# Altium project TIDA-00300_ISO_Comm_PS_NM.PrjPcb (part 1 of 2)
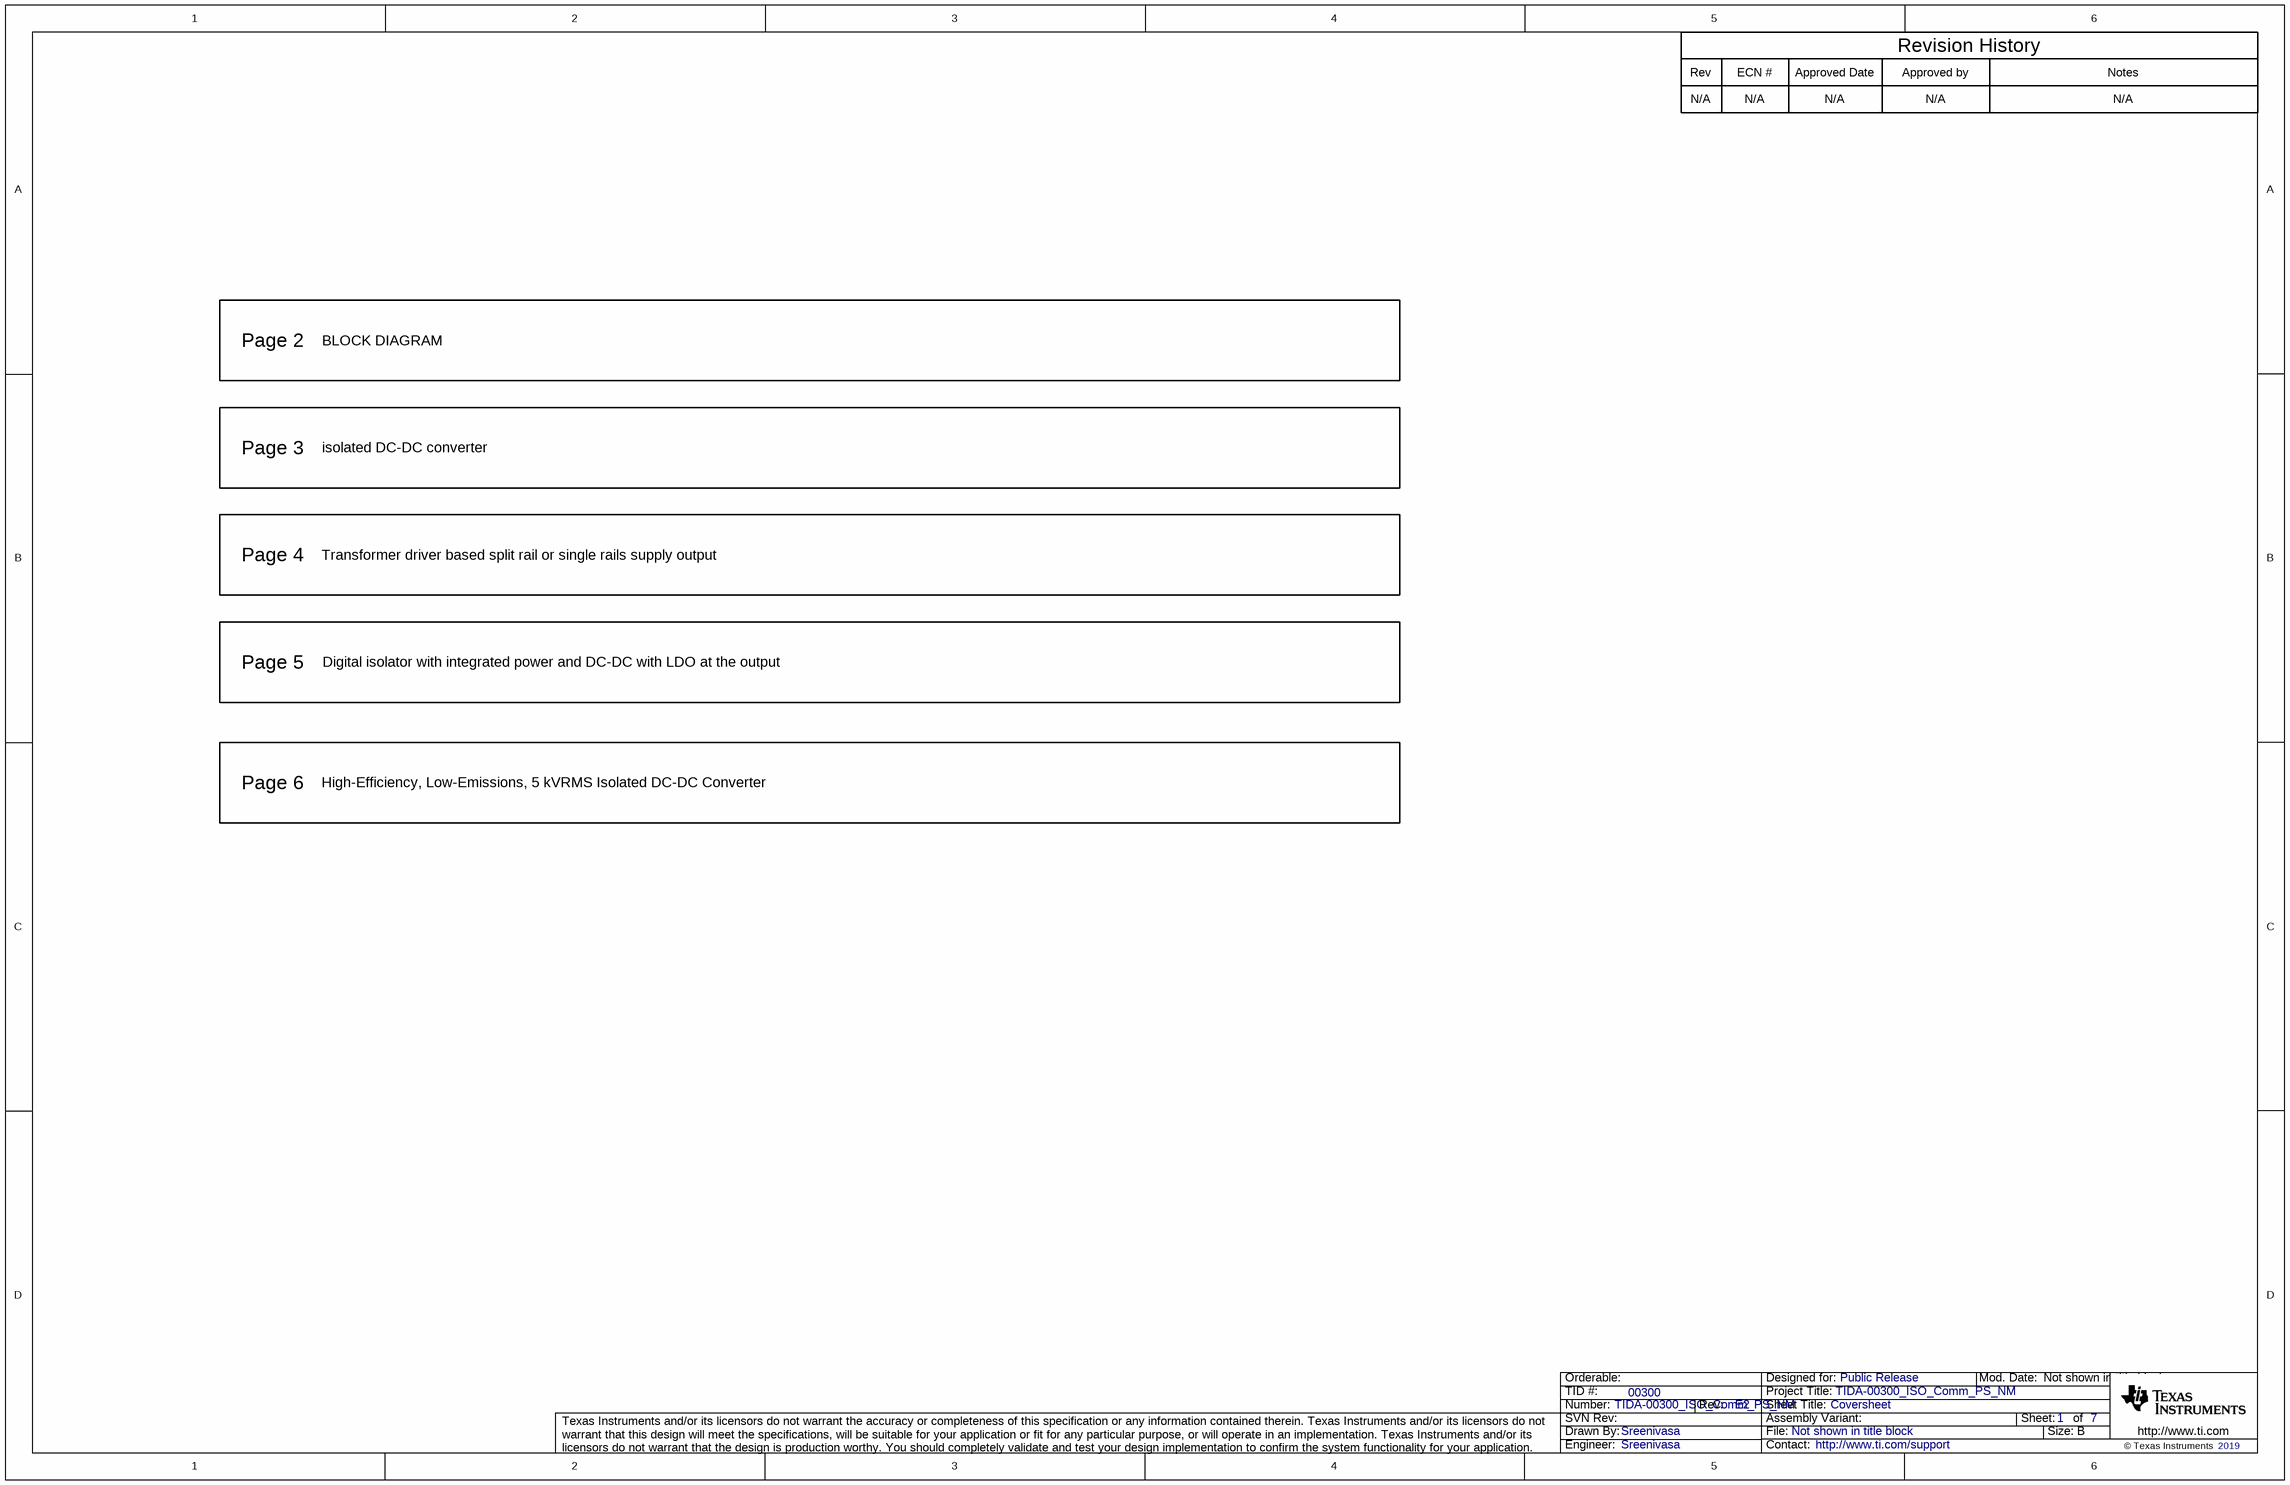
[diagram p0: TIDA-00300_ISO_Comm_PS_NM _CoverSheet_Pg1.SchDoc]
CopyrightYear: 2019; PCB_Layout: Avinash N; PCB_Rev: E2; PRJ_Customer: Public Release; PRJ_Engineer: Sreenivasa; PRJ_Number: TIDA-00300_ISO_Comm_PS_NM; PRJ_Title: TIDA-00300_ISO_Comm_PS_NM; SCH_Rev: E2; TechSupport: http://www.ti.com/support; TID: 00300
7 sheets, 304 parts. Net scope: global (net labels, ports and power ports of the same name join across sheets).
Board file: TIDA-00300_ISO_Comm_PS_NM.PcbDoc
Sheets:
  TIDA-00300_ISO_Comm_PS_NM _CoverSheet_Pg1.SchDoc
  TIDA-00300_ISO_Comm_PS_NM_ Block Diagram_Pg2.SchDoc
  TIDA-00300_ISO_Comm_PS_NM_Pg3.SchDoc
  TIDA-00300_ISO_Comm_PS_NM_Pg4.SchDoc
  TIDA-00300_ISO_Comm_PS_NM_Pg5.SchDoc
  TIDA-00300_ISO_Comm_PS_NM_Pg6.SchDoc
  TIDA-00300_ISO_Comm_PS_NM_EVM_Hardware_Pg7.SchDoc

## Sheet TIDA-00300_ISO_Comm_PS_NM _CoverSheet_Pg1.SchDoc: Coversheet
size 431 x 279 mm; Date: Not shown in title block; ApprovedBy: Not shown in title block; CheckedBy: Not shown in title block; Author: Not shown in title block; CompanyName: Not shown in title block; DrawnBy: Sreenivasa; Engineer: Not shown in title block; Organization: Not shown in title block; Address1: Not shown in title block; Address2: Not shown in title block; Address3: Not shown in title block; Address4: Not shown in title block; DocumentNumber: 1; Revision: Use project parameter SCH_Rev; SheetNumber: 1; SheetTotal: 7; PageSetup: Record=PageOptions¦CenterHorizontal=True¦CenterVertical=True¦PrintScale=1.00¦XCorrection=1.00¦YCorrection=1.00¦PrintKind=0¦BorderSize=5000000¦LeftOffset=0¦BottomOffset=0¦Orientation=2¦PaperLength=1000¦PaperWidth=1000¦Scale=100¦PaperSource=15¦PrintQuality=600¦MediaType=1¦DitherType=10¦PaperKind=Letter¦PrintScaleMode=1

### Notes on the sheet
- Rev
- N/A
- ECN #
- Approved Date
- Approved by
- Revision History
- Notes
- Page 2
- BLOCK DIAGRAM
- Page 3
- isolated DC-DC converter
- Page 4
- Transformer driver based split rail or single rails supply output
- Page 5
- Digital isolator with integrated power and DC-DC with LDO at the output
- Page 6
- High-Efficiency, Low-Emissions, 5 kVRMS Isolated DC-DC Converter

## Sheet TIDA-00300_ISO_Comm_PS_NM_ Block Diagram_Pg2.SchDoc: Block Diagram
size 431 x 279 mm; Date: Not shown in title block; ApprovedBy: Not shown in title block; CheckedBy: Not shown in title block; Author: Not shown in title block; CompanyName: Not shown in title block; DrawnBy: Sreenivasa; Engineer: Sreenivasa; Organization: Not shown in title block; Address1: Not shown in title block; Address2: Not shown in title block; Address3: Not shown in title block; Address4: Not shown in title block; DocumentNumber: 1; Revision: Use project parameter SCH_Rev; SheetNumber: 2; SheetTotal: 7; PageSetup: Record=PageOptions¦CenterHorizontal=True¦CenterVertical=True¦PrintScale=1.00¦XCorrection=1.00¦YCorrection=1.00¦PrintKind=0¦BorderSize=5000000¦LeftOffset=0¦BottomOffset=0¦Orientation=2¦PaperLength=1000¦PaperWidth=1000¦Scale=100¦PaperSource=15¦PrintQuality=600¦MediaType=1¦DitherType=10¦PaperKind=Letter¦PrintScaleMode=1
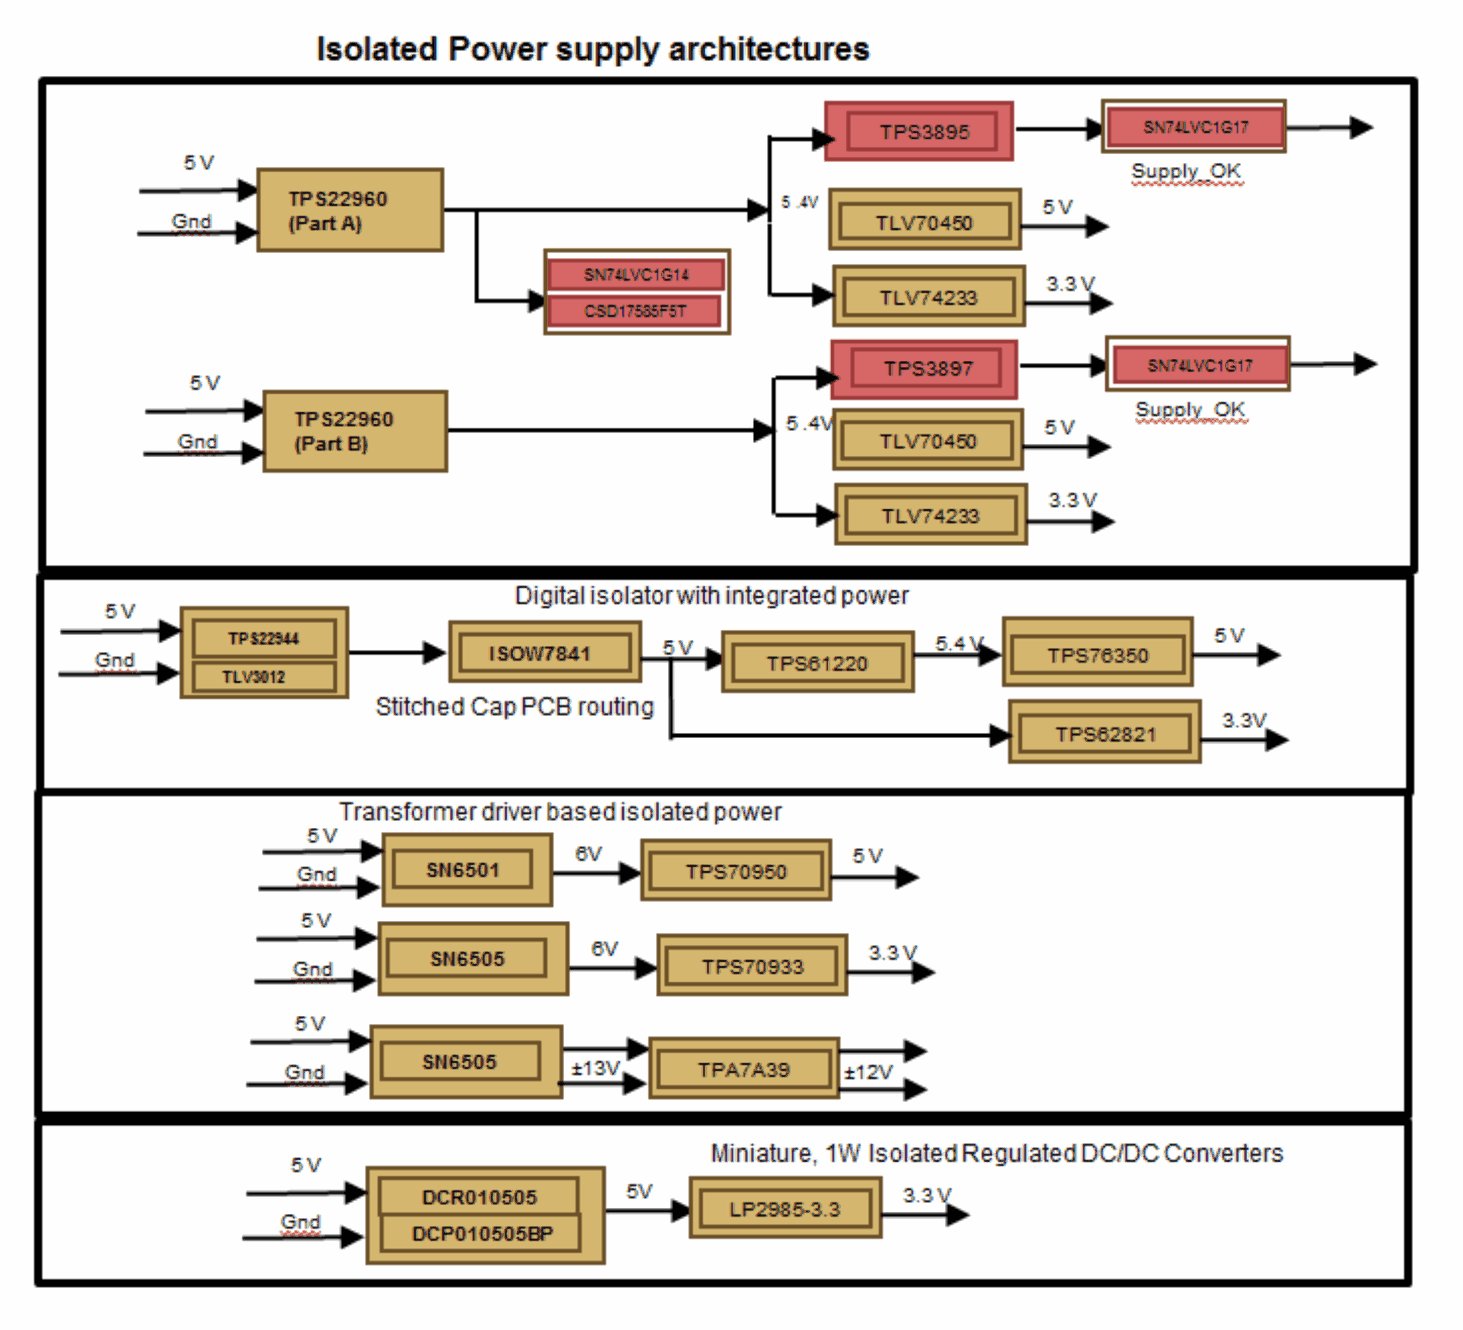
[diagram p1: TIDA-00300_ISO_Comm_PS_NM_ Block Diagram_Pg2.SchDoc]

## Sheet TIDA-00300_ISO_Comm_PS_NM_Pg3.SchDoc
size 431 x 279 mm; Date: Not shown in title block; ApprovedBy: Not shown in title block; CheckedBy: Not shown in title block; Author: Not shown in title block; CompanyName: Not shown in title block; DrawnBy: Sreenivasa; Engineer: Not shown in title block; Organization: Not shown in title block; Address1: Not shown in title block; Address2: Not shown in title block; Address3: Not shown in title block; Address4: Not shown in title block; DocumentNumber: 1; Revision: Use project parameter SCH_Rev; SheetNumber: 3; SheetTotal: 7; PageSetup: Record=PageOptions¦CenterHorizontal=True¦CenterVertical=True¦PrintScale=0.62¦XCorrection=1.00¦YCorrection=1.00¦PrintKind=0¦BorderSize=5000000¦LeftOffset=0¦BottomOffset=0¦Orientation=2¦PaperLength=1000¦PaperWidth=1000¦Scale=100¦PaperSource=15¦PrintQuality=600¦MediaType=1¦DitherType=10¦PrintScaleMode=1¦PaperKind=Letter
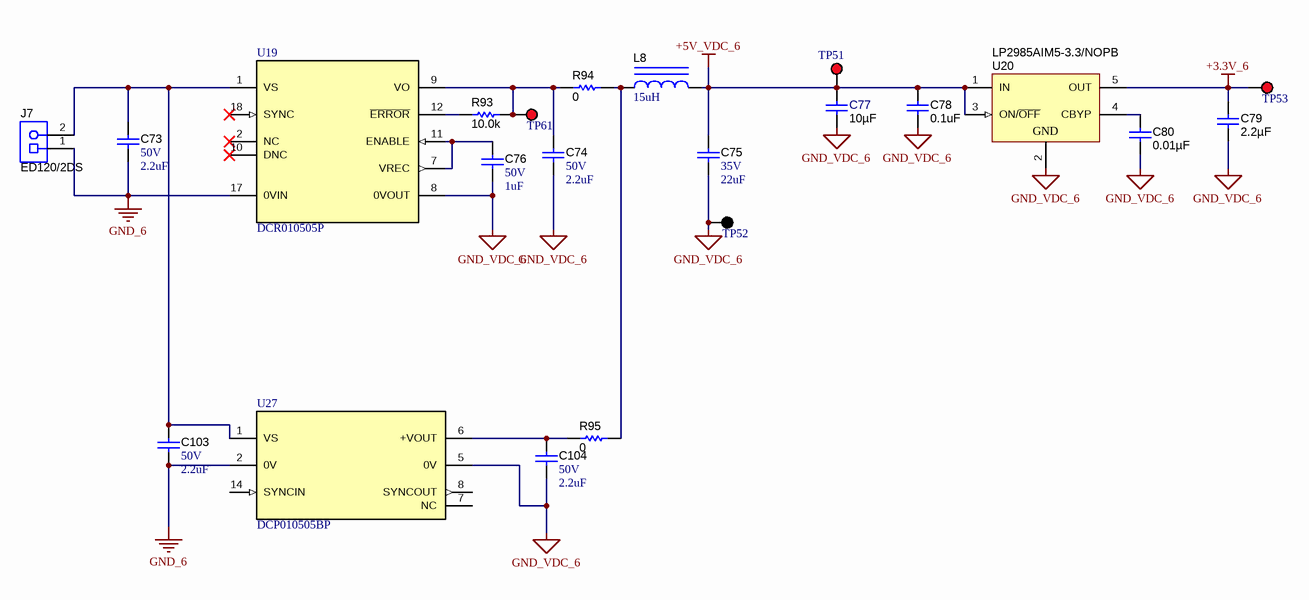
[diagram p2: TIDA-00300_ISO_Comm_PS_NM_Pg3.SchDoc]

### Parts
C73  VDC_V: 50V  ValueDisplayed: 2.2uF  [0805_HV]  (hidden comment: C2012X5R1H225K125AB)
C74  VDC_V: 50V  ValueDisplayed: 2.2uF  [0805_HV]  (hidden comment: C2012X5R1H225K125AB)
C75  VDC_V: 35V  ValueDisplayed: 22uF  [0805_HV]  (hidden comment: C2012X5R1V226M125AC)
C76  VDC_V: 50V  ValueDisplayed: 1uF  [0603]  (hidden comment: UMK107AB7105KA-T)
C77  ValueDisplayed: 10µF  [0603]  (hidden comment: C1608X5R1A106M)
C78  value 0.1uF  [0402]  (hidden comment: GRM155R71C104JA88D)
C79  ValueDisplayed: 2.2µF  [0603]  (hidden comment: C0603C225K8PACTU)
C80  ValueDisplayed: 0.01µF  [0603]  (hidden comment: C1608C0G1E103J)
C103  VDC_V: 50V  ValueDisplayed: 2.2uF  [0805_HV]  (hidden comment: C2012X5R1H225K125AB)
C104  VDC_V: 50V  ValueDisplayed: 2.2uF  [0805_HV]  (hidden comment: C2012X5R1H225K125AB)
J7  ED120/2DS  [CONN_ED120-2DS]
L8  ValueDisplayed: 15uH  [LQH3NP_G0]  (hidden comment: LQH3NPN150NG0)
R93  ValueDisplayed: 10.0k  [0402]  (hidden comment: CRCW040210K0FKED)
R94  value 0  [0603]  (hidden comment: CRCW06030000Z0EA)
R95  value 0  [0603]  (hidden comment: CRCW06030000Z0EA)
TP51  5000  [Keystone5000]  (value not drawn)
TP52  5001  [Keystone5001]  (value not drawn)
TP53  5000  [Keystone5000]  (value not drawn)
TP61  5000  [Keystone5000]  (value not drawn)
U19  DCR010505P  [NVE0010A]
U20  LP2985AIM5-3.3/NOPB  [MF05A_N]
U27  DCP010505BP  [NVA0007A]

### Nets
+3.3V_6: C79.1 TP53.1 U20.5(OUT)
+5V_VDC_6: C75.1 C77.1 C78.1 L8.2 TP51.1 U20.1(IN) U20.3(ON/~{OFF})
GND_6: C73.2 C103.2 J7.1 U19.17(0VIN) U27.2(0V)
GND_VDC_6: C74.2 C75.2 C76.2 C77.2 C78.2 C79.2 C80.2 C104.2 TP52.1 U19.8(0VOUT) U20.2(GND) U27.5(0V)
NetC73_1: C73.1 C103.1 J7.2 U19.1(VS) U27.1(VS)
NetC74_1: C74.1 R93.2 R94.2 TP61.1 U19.9(VO)
NetC76_1: C76.1 U19.7(VREC) U19.11(ENABLE)
NetC80_1: C80.1 U20.4(CBYP)
NetC104_1: C104.1 R95.2 U27.6(+VOUT)
NetL8_1: L8.1 R94.1 R95.1
NetR93_1: R93.1 U19.12(~{ERROR})

Not connected (* = marked no-connect by the designer): U19 2(NC)* 10(DNC)* 18(SYNC)*; U27 7(NC) 8(SYNCOUT) 14(SYNCIN)

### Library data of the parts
C73 C74 C103 C104 = CMP-0007836-1: CAP, CERM, 2.2 uF, 50 V, +/- 10%, X5R, 0805; Manufacturer: TDK; TaMin_C: -55°C; ESR_ohm: 3.66m; Polarized: N; SizeAreaWB_mm2: 6.75; Value1: 0.00366 ohm; U/M: EA; Value: 2.2uF; TaMax_C: 85°C; SizeZ_mm: 1.45; SizeX_mm: 2; SizeY_mm: 1.25; Cap_Case: 0805; SizeArea_mm2: 2.5; Cap_F: 2.2µF; IRMS_A: 3.41207A; AEC Category: Q200
C75 = CMP-0007844-1: CAP, CERM, 22 uF, 35 V, +/- 20%, X5R, 0805; Manufacturer: TDK; TaMin_C: -55°C; ESR_ohm: 2.05m; Polarized: N; SizeAreaWB_mm2: 6.75; Value1: 0.00205 ohm; U/M: EA; Value: 22uF; TaMax_C: 85°C; SizeZ_mm: 1.45; SizeX_mm: 2; SizeY_mm: 1.25; Cap_Case: 0805; SizeArea_mm2: 2.5; Cap_F: 22µF; IRMS_A: 4.55587A; AEC Category: Q200
C76 = CMP-0007508-1: CAP, CERM, 1 uF, 50 V, +/- 10%, X7R, 0603; Manufacturer: Taiyo Yuden; TaMin_C: -55°C; Polarized: N; SizeAreaWB_mm2: 4.68; Value1: Unknown; U/M: EA; Value: 1uF; TaMax_C: 125°C; SizeZ_mm: 1; SizeX_mm: 1.6; SizeY_mm: 0.8; SizeArea_mm2: 1.28; Cap_F: 1µF; AEC Category: Q200
C77 = C1608X5R1A106M: CAP, CERM, 10uF, 10V, +/-20%, X5R, 0603; Manufacturer: TDK; Polarized: N; CompType: Capacitor; U/M: EA; Cap_F: 0.00001; Tolerance_%: 20; ESR_Ohm: 0.0078; Value1: 0.0078 ohm; VDC_V: 10; IRMS_A: 1.85; TaMin_C: -55; TaMax_C: 85
C78 = 0402YC132KAT2A: CAP CER 0.1UF 16V 5% X7R 0402; Manufacturer: Murata Electronics North America; Polarized: N; CompType: Capacitor; U/M: EA; Cap_F: 0.0000000013; Tolerance_%: 10; VDC_V: 16; TaMin_C: -55; TaMax_C: 125
C79 = C0603C225K8PACTU: CAP, CERM, 2.2uF, 10V, +/-10%, X5R, 0603; Manufacturer: Kemet; Polarized: N; CompType: Capacitor; U/M: EA; Cap_F: 0.0000022; Tolerance_%: 10; Value1: Unknown; TaMin_C: -55; TaMax_C: 85
C80 = C1608C0G1E103J: CAP, CERM, 0.01uF, 25V, +/-5%, C0G/NP0, 0603; Manufacturer: TDK; Polarized: N; CompType: Capacitor; U/M: EA; Cap_F: 0.00000001; Tolerance_%: 5; VDC_V: 25; TaMin_C: -55; TaMax_C: 125
J7 = ED120/2DS: TERMINAL BLOCK 5.08MM VERT 2POS, TH; Manufacturer: On-Shore Technology; SymbolCreator: a0412235; U/M: EA
L8 = CMP-0058850-1: Inductor, Wirewound, Ferrite, 15 uH, 0.37 A, 0.91 ohm, SMD; Manufacturer: MuRata; Isat: 0.37A @ 30% inductance drop; Irms: 0.475A @ 40C rise; Green_Lifecycle: Not Set; SizeAreaWB_mm2: 16; DCR_ohm: 0.91; Green_REACh: Incomplete; Value: 15uH; Imax_A: 370mA; SizeZ_mm: 1; SizeX_mm: 3; Value2: 0.37A; SizeArea_mm2: 9; Ind_H: 15µH; AEC Category: Q200
R93 = CRCW040210K0FKED: RES, 10.0 k, 1%, 0.063 W, 0402; Manufacturer: Vishay-Dale; CompType: Resistor; Value: 10.0k; Res_ohm: 10000; Value_Code: 10k0; Tolerance_%: 1; Power_W: 0.063; Value2: 0.063W; VDC_V: 50; TempCo: 100 ppm/C; SizeArea_mm2: 0.5; SizeZ_mm: 0.6; EIA_Code: E96; U/M: EA; AEC Category: Q200; Green_Lifecycle: Active; Green_REACh: Passed
R94 R95 = CRCW06030000Z0EA: RES, 0 ohm, 5%, 0.1W, 0603; Manufacturer: Vishay-Dale; CompType: Resistor; Value_Code: 0000; Tolerance_%: 5; Power_W: 0.1; VDC_V: 75; TempCo: 200 ppm/C; EIA_Code: E24; U/M: EA
TP51 TP53 TP61 = 5000: Test Point, Miniature, Red, TH; Manufacturer: Keystone; CompType: Test Point Loop; ContactFinish: Silver; Green_Lifecycle: Active; Green_REACh: Passed
TP52 = 5001: Test Point, Miniature, Black, TH; Manufacturer: Keystone; CompType: Test Point Loop; ContactFinish: Silver; Green_Lifecycle: Active; Green_REACh: Passed
U19 = CMP-0030829-1: Miniature, 1 W Isolated Regulated DC-DC Converter, -40 to 85 degC, 10-pin DIP (NVE10), Pb-Free (RoHS); Manufacturer: Texas Instruments; Vout(Max)(V): 5.1; Vin(Min)(V): 4.5; Regulated Outputs(#): 1; Vout(Min)(V): 4.9; SubFamily: 1 W & 2 W Miniature; Iout(Max)(A): 0.2; Vin(Max)(V): 5.5
U20 = LP2985AIM5-3.3/NOPB: Micropower 150 mA Low-Noise Ultra Low-Dropout Regulator, 5-pin SOT-23, Pb-Free; Manufacturer: Texas Instruments; PackageTopMarking: L0RA*XTT; PowerWise: N; CompType: LDO IC
U27 = CMP-0030762-1: Miniature, 1 W Isolated Unregulated DC-DC Converter, -40 to 100 degC, 7-pin DIP (NVA7), Pb-Free (RoHS); Manufacturer: Texas Instruments; SubFamily: 1 W & 2 W Miniature; Vin(Max)(V): 5.5; Vout(Max)(V): 5.25; Vin(Min)(V): 4.5; Regulated Outputs(#): 1; Vout(Min)(V): 4.75; Iout(Max)(A): 0.2

## Sheet TIDA-00300_ISO_Comm_PS_NM_Pg4.SchDoc
size 431 x 279 mm; Date: Not shown in title block; ApprovedBy: Not shown in title block; CheckedBy: Not shown in title block; Author: Not shown in title block; CompanyName: Not shown in title block; DrawnBy: Sreenivasa; Engineer: Not shown in title block; Organization: Not shown in title block; Address1: Not shown in title block; Address2: Not shown in title block; Address3: Not shown in title block; Address4: Not shown in title block; DocumentNumber: 1; Revision: Use project parameter SCH_Rev; SheetNumber: 4; SheetTotal: 7; PageSetup: Record=PageOptions¦CenterHorizontal=True¦CenterVertical=True¦PrintScale=0.62¦XCorrection=1.00¦YCorrection=1.00¦PrintKind=0¦BorderSize=5000000¦LeftOffset=0¦BottomOffset=0¦Orientation=2¦PaperLength=1000¦PaperWidth=1000¦Scale=100¦PaperSource=15¦PrintQuality=600¦MediaType=1¦DitherType=10¦PrintScaleMode=1¦PaperKind=Letter
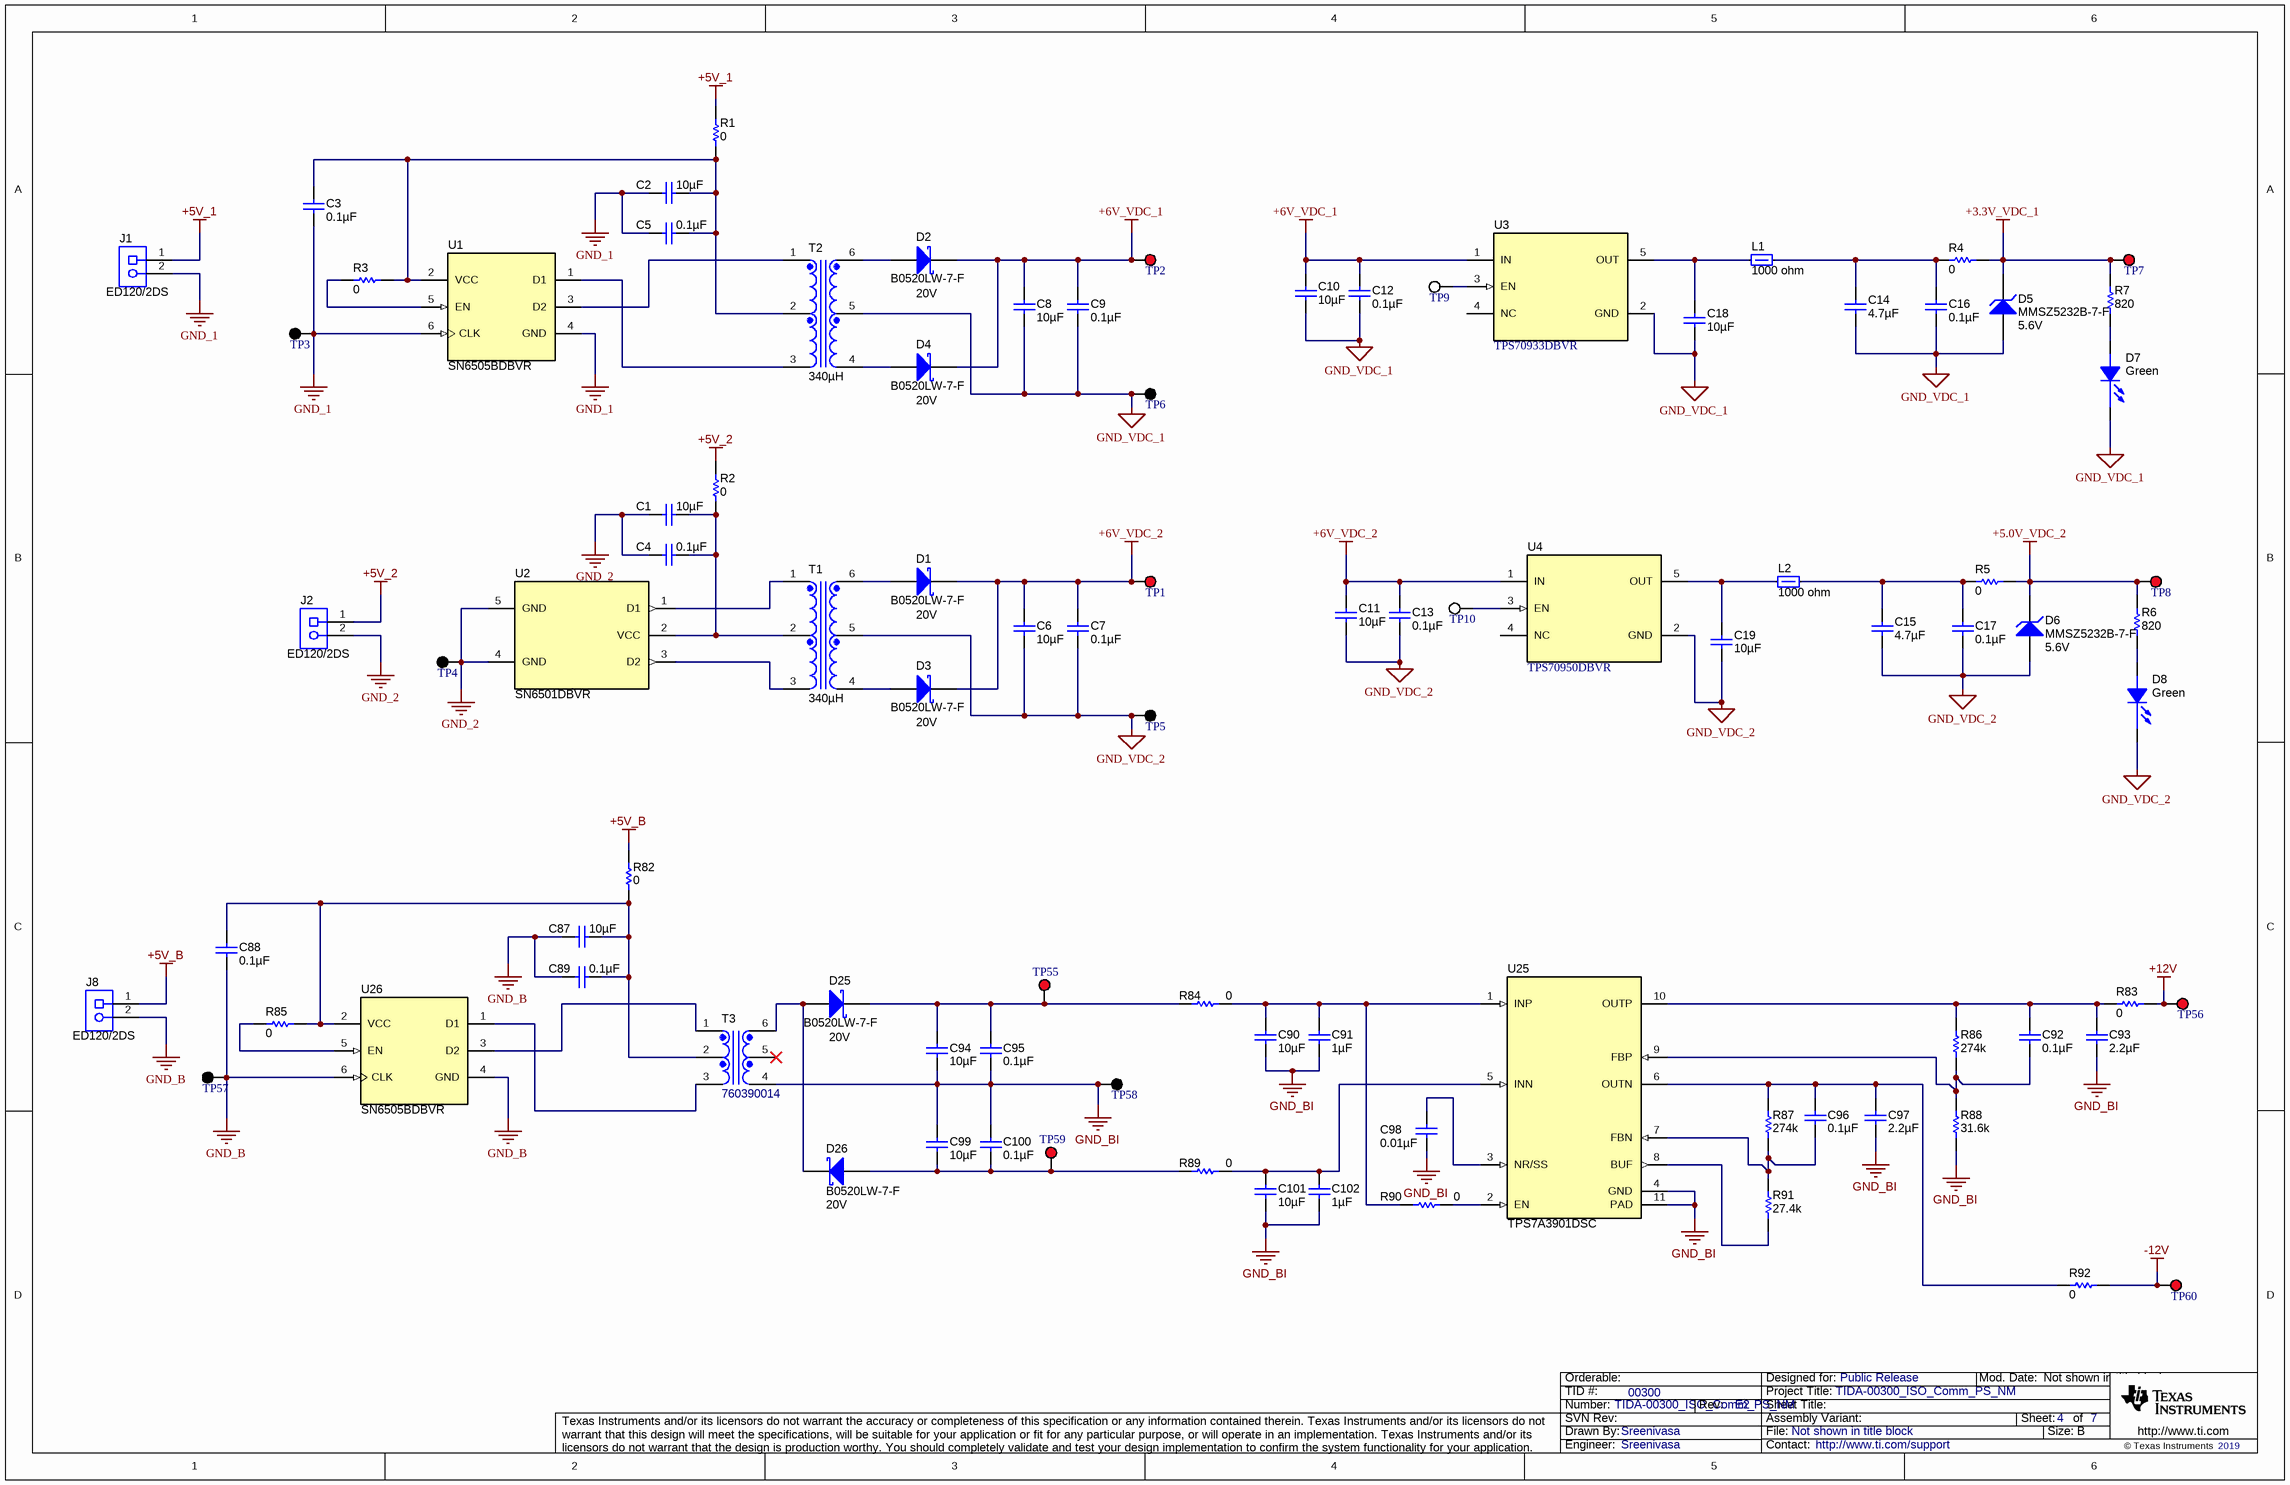
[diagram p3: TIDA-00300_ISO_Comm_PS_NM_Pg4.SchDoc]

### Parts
C1  ValueDisplayed: 10µF  [1210]
C2  ValueDisplayed: 10µF  [1210]
C3  ValueDisplayed: 0.1µF  [0603]
C4  ValueDisplayed: 0.1µF  [0603]
C5  ValueDisplayed: 0.1µF  [0603]
C6  ValueDisplayed: 10µF  [1210]
C7  ValueDisplayed: 0.1µF  [0603]
C8  ValueDisplayed: 10µF  [1210]
C9  ValueDisplayed: 0.1µF  [0603]
C10  ValueDisplayed: 10µF  [1210]
C11  ValueDisplayed: 10µF  [1210]
C12  ValueDisplayed: 0.1µF  [0603]
C13  ValueDisplayed: 0.1µF  [0603]
C14  ValueDisplayed: 4.7µF  [0805_HV]
C15  ValueDisplayed: 4.7µF  [0805_HV]
C16  ValueDisplayed: 0.1µF  [0603]
C17  ValueDisplayed: 0.1µF  [0603]
C18  ValueDisplayed: 10µF  [1210]
C19  ValueDisplayed: 10µF  [1210]
C87  ValueDisplayed: 10µF  [1210]
C88  ValueDisplayed: 0.1µF  [0603]
C89  ValueDisplayed: 0.1µF  [0603]
C90  ValueDisplayed: 10µF  [1206_180]  (hidden comment: C1210C106M5RACTU)
C91  ValueDisplayed: 1µF  [0603]  (hidden comment: C1608X7R1E105K080AB)
C92  ValueDisplayed: 0.1µF  [0603]  (hidden comment: GMK107BJ104KAHT)
C93  ValueDisplayed: 2.2µF  [0805_HV]  (hidden comment: C0805C225K8RACTU)
C94  ValueDisplayed: 10µF  [1210]
C95  ValueDisplayed: 0.1µF  [0603]
C96  ValueDisplayed: 0.1µF  [0603]  (hidden comment: GMK107BJ104KAHT)
C97  ValueDisplayed: 2.2µF  [0805_HV]  (hidden comment: C0805C225K8RACTU)
C98  ValueDisplayed: 0.01µF  [0603]  (hidden comment: GRM188R70J103KA01D)
C99  ValueDisplayed: 10µF  [1210]
C100  ValueDisplayed: 0.1µF  [0603]
C101  ValueDisplayed: 10µF  [1206_180]  (hidden comment: C1210C106M5RACTU)
C102  ValueDisplayed: 1µF  [0603]  (hidden comment: C1608X7R1E105K080AB)
D1  B0520LW-7-F  value 20V  [SOD-123]
D2  B0520LW-7-F  value 20V  [SOD-123]
D3  B0520LW-7-F  value 20V  [SOD-123]
D4  B0520LW-7-F  value 20V  [SOD-123]
D5  MMSZ5232B-7-F  value 5.6V  [SOD-123]
D6  MMSZ5232B-7-F  value 5.6V  [SOD-123]
D7  value Green  [LED0603AA]
D8  value Green  [LED0603AA]
D25  B0520LW-7-F  value 20V  [SOD-123]
D26  B0520LW-7-F  value 20V  [SOD-123]
J1  ED120/2DS  [CONN_ED120-2DS]
J2  ED120/2DS  [CONN_ED120-2DS]
J8  ED120/2DS  [CONN_ED120-2DS]
L1  value 1000 ohm  [MMZ1608_095]  (hidden comment: MMZ1608B102CTA00)
L2  value 1000 ohm  [MMZ1608_095]  (hidden comment: MMZ1608B102CTA00)
R1  value 0  [0603]  (hidden comment: CRCW06030000Z0EA)
R2  value 0  [0603]  (hidden comment: CRCW06030000Z0EA)
R3  value 0  [0603]  (hidden comment: CRCW06030000Z0EA)
R4  value 0  [0603]  (hidden comment: CRCW06030000Z0EA)
R5  value 0  [0603]  (hidden comment: CRCW06030000Z0EA)
R6  ValueDisplayed: 820  [0603]  (hidden comment: RC0603FR-07820RL)
R7  ValueDisplayed: 820  [0603]  (hidden comment: RC0603FR-07820RL)
R82  value 0  [0603]  (hidden comment: CRCW06030000Z0EA)
R83  ValueDisplayed: 0  [0603]  (hidden comment: CRCW06030000Z0EA)
R84  ValueDisplayed: 0  [0603]  (hidden comment: CRCW06030000Z0EA)
R85  value 0  [0603]  (hidden comment: CRCW06030000Z0EA)
R86  ValueDisplayed: 274k  [0603]  (hidden comment: CRCW0603274KFKEA)
R87  ValueDisplayed: 274k  [0603]  (hidden comment: CRCW0603274KFKEA)
R88  ValueDisplayed: 31.6k  [0603]  (hidden comment: CRCW060331K6FKEA)
R89  ValueDisplayed: 0  [0603]  (hidden comment: CRCW06030000Z0EA)
R90  ValueDisplayed: 0  [0603]  (hidden comment: CRCW06030000Z0EA)
R91  ValueDisplayed: 27.4k  [0603]  (hidden comment: CRCW060327K4FKEA)
R92  ValueDisplayed: 0  [0603]  (hidden comment: CRCW06030000Z0EA)
T1  ValueDisplayed: 340µH  [Wurth_750313638]  (hidden comment: 750313638)
T2  ValueDisplayed: 340µH  [Wurth_750313638]  (hidden comment: 750313638)
T3  760390014  [Wurth_760390013]
TP1  5000  [Keystone5000]  (value not drawn)
TP2  5000  [Keystone5000]  (value not drawn)
TP3  5001  [Keystone5001]  (value not drawn)
TP4  5001  [Keystone5001]  (value not drawn)
TP5  5001  [Keystone5001]  (value not drawn)
TP6  5001  [Keystone5001]  (value not drawn)
TP7  5000  [Keystone5000]  (value not drawn)
TP8  5000  [Keystone5000]  (value not drawn)
TP9  5002  [Keystone5002]  (value not drawn)
TP10  5002  [Keystone5002]  (value not drawn)
TP55  5000  [Keystone5000]  (value not drawn)
TP56  5000  [Keystone5000]  (value not drawn)
TP57  5001  [Keystone5001]  (value not drawn)
TP58  5001  [Keystone5001]  (value not drawn)
TP59  5000  [Keystone5000]  (value not drawn)
TP60  5000  [Keystone5000]  (value not drawn)
U1  SN6505BDBVR  [DBV0006A_N]
U2  SN6501DBVR  [DBV0005A_N]
U3  TPS70933DBVR  [DBV0005A_N]
U4  TPS70950DBVR  [DBV0005A_N]
U25  TPS7A3901DSC  [DSC0010J]
U26  SN6505BDBVR  [DBV0006A_N]

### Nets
+3.3V_VDC_1: D5.1(K) R4.2 R7.2 TP7.1
+5.0V_VDC_2: D6.1(K) R5.2 R6.2 TP8.1
+5V_1: J1.1 R1.2
+5V_2: J2.1 R2.2
+5V_B: J8.1 R82.2
+6V_VDC_1: C8.1 C9.1 C10.2 C12.1 D2.1(K) D4.1(K) TP2.1 U3.1(IN)
+6V_VDC_2: C6.1 C7.1 C11.2 C13.1 D1.1(K) D3.1(K) TP1.1 U4.1(IN)
+12V: R83.2 TP56.1
-12V: R92.2 TP60.1
GND_1: C2.1 C3.1 C5.1 J1.2 TP3.1 U1.4(GND) U1.6(CLK)
GND_2: C1.1 C4.1 J2.2 TP4.1 U2.4(GND) U2.5(GND)
GND_B: C87.1 C88.1 C89.1 J8.2 TP57.1 U26.4(GND) U26.6(CLK)
GND_BI: C90.1 C91.2 C93.2 C94.2 C95.2 C97.2 C98.2 C99.1 C100.1 C101.1 C102.2 R88.1 T3.4 TP58.1 U25.4(GND) U25.11(PAD)
GND_VDC_1: C8.2 C9.2 C10.1 C12.2 C14.1 C16.2 C18.1 D5.2(A) D7.1(C) T2.5 TP6.1 U3.2(GND)
GND_VDC_2: C6.2 C7.2 C11.1 C13.2 C15.1 C17.2 C19.1 D6.2(A) D8.1(C) T1.5 TP5.1 U4.2(GND)
NetC1_2: C1.2 C4.2 R2.1 T1.2 U2.2(VCC)
NetC2_2: C2.2 C3.2 C5.2 R1.1 R3.1 T2.2 U1.2(VCC)
NetC14_2: C14.2 C16.1 L1.2 R4.1
NetC15_2: C15.2 C17.1 L2.2 R5.1
NetC18_2: C18.2 L1.1 U3.5(OUT)
NetC19_2: C19.2 L2.1 U4.5(OUT)
NetC87_2: C87.2 C88.2 C89.2 R82.1 R85.1 T3.2 U26.2(VCC)
NetC90_2: C90.2 C91.1 R84.2 R90.1 U25.1(INP)
NetC92_1: C92.1 C93.1 R83.1 R86.2 U25.10(OUTP)
NetC92_2: C92.2 R86.1 R88.2 U25.9(FBP)
NetC94_1: C94.1 C95.1 D25.1(K) R84.1 TP55.1
NetC96_1: C96.1 C97.1 R87.2 R92.1 U25.6(OUTN)
NetC96_2: C96.2 R87.1 R91.2 U25.7(FBN)
NetC98_1: C98.1 U25.3(NR/SS)
NetC99_2: C99.2 C100.2 D26.2(A) R89.1 TP59.1
NetC101_2: C101.2 C102.1 R89.2 U25.5(INN)
NetD1_2: D1.2(A) T1.6
NetD2_2: D2.2(A) T2.6
NetD3_2: D3.2(A) T1.4
NetD4_2: D4.2(A) T2.4
NetD7_2: D7.2(A) R7.1
NetD8_2: D8.2(A) R6.1
NetD25_2: D25.2(A) D26.1(K) T3.6
NetR3_2: R3.2 U1.5(EN)
NetR85_2: R85.2 U26.5(EN)
NetR90_2: R90.2 U25.2(EN)
NetR91_1: R91.1 U25.8(BUF)
NetT1_1: T1.1 U2.1(D1)
NetT1_3: T1.3 U2.3(D2)
NetT2_1: T2.1 U1.3(D2)
NetT2_3: T2.3 U1.1(D1)
NetT3_1: T3.1 U26.3(D2)
NetT3_3: T3.3 U26.1(D1)
NetTP9_1: TP9.1 U3.3(EN)
NetTP10_1: TP10.1 U4.3(EN)

Not connected (* = marked no-connect by the designer): T3 5*; U3 4(NC); U4 4(NC)

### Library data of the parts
C1 C2 C6 C8 C10 C11 C18 C19 C87 C94 C99 = GMK325AB7106MM-T: CAP, CERM, 10uF, 35V, +/-20%, X7R, 1210; Manufacturer: Taiyo Yuden; Polarized: N; CompType: Capacitor; U/M: EA; Cap_F: 0.00001; Tolerance_%: 20; Value1: Unknown; VDC_V: 35; TaMin_C: -55; TaMax_C: 125
C3-C5 C7 C9 C12 C13 C16 C17 C88 C89 C95 C100 = C0603C104K5RACTU: CAP, CERM, 0.1uF, 50V, +/-10%, X7R, 0603; Manufacturer: Kemet; Polarized: N; CompType: Capacitor; U/M: EA; Cap_F: 0.0000001; Tolerance_%: 10; Value1: Unknown; VDC_V: 50; TaMin_C: -55; TaMax_C: 125
C14 C15 = C2012X5R1H475K125AB: 4.7µF ±10% 50V X5R Ceramic Capacitor -55°C ~ 85°C; PartNumber: GRM21BR61H475KE51L; Manufacturer: TDK; Polarized: N; Value: 4.7uF; U/M: EA; Cap_F: 0.0000047; Tolerance_%: 10; Value1: Unknown; VDC_V: 50; TaMin_C: -55; TaMax_C: 85; Cap_Case: 0805
C90 C101 = CL31B106KBHNNNE: CAP, CERM, 10µF ±20% 50V Ceramic Capacitor X7R 1210; Manufacturer: Kemet; Polarized: N; Value: 10uF; U/M: EA; Cap_F: 0.00001; Tolerance_%: 10; Value1: Unknown; VDC_V: 50; TaMin_C: -55; TaMax_C: 125; Cap_Case: 1206; SizeArea_mm2: 5.12; SizeAreaWB_mm2: 10.92; SizeX_mm: 3.2; SizeY_mm: 1.6; SizeZ_mm: 1.8; AEC Category: Q200
C91 C102 = 885012206052: CAP, CERM,  1µF ±10% 25V Ceramic Capacitor X7R 0603; Manufacturer: TDK; Polarized: N; Value: 1uF; U/M: EA; Cap_F: 0.000001; Tolerance_%: 10; Value1: Unknown; VDC_V: 16; Value2: 16V; TaMin_C: -55; TaMax_C: 125; SizeArea_mm2: 1.28; SizeAreaWB_mm2: 4.68; SizeX_mm: 1.6; SizeY_mm: 0.8; SizeZ_mm: 1; AEC Category: Q200; Green_Lifecycle: Active; Green_REACh: Passed
C92 C96 = 06033C104JAT2A: 0.1µF ±10% 35V Ceramic Capacitor X5R 0603; Manufacturer: Taiyo Yuden; Polarized: N; Value: 0.1uF; U/M: EA; Cap_F: 0.0000001; Tolerance_%: 5; ESR_ohm: 0.05; Value1: 0.05 ohm; VDC_V: 25; Value2: 25V; TempCo: X7R; TaMin_C: -55; TaMax_C: 125; SizeArea_mm2: 1.28; SizeAreaWB_mm2: 4.68; SizeX_mm: 1.6; SizeY_mm: 0.8; SizeZ_mm: 1; AEC Category: Q200
C93 C97 = C0805C225K8RACTU: CAP, CERM, 2.2uF, 10V, +/-10%, X7R, 0805; Manufacturer: Kemet; Polarized: N; CompType: Capacitor; U/M: EA; Cap_F: 0.0000022; Tolerance_%: 10; ESR_Ohm: 0.008; Value1: 0.008 ohm; IRMS_A: 15.55; TaMin_C: -55; TaMax_C: 125; Cap_Case: 0805
C98 = GRM188R70J103KA01D: CAP, CERM, 0.01 µF, 6.3 V, +/- 10%, X7R, 0603; Manufacturer: MuRata; Polarized: N; CompType: Capacitor; Value: 0.01uF; U/M: EA; Cap_F: 0.00000001; Tolerance_%: 10; Value1: Unknown; VDC_V: 6.3; Value2: 6.3V; TaMin_C: -55; TaMax_C: 125
D1-D4 D25 D26 = MBR0520LT1G: Diode, Schottky, 20V, 0.5A, SOD-123; Manufacturer: Diodes Inc; U/M: EA; Vf_V: 0.385; Value2: 0.385V; Io_A: 0.5; Vr_V: 20; TJmax_C: 125; RJC_CperW: 150
D5 D6 = MMSZ5232B-7-F: Diode, Zener, 5.6 V, 500 mW, SOD-123; Manufacturer: Diodes Inc.; SymbolCreator: a0412235; U/M: EA; Power_W: 0.5; Vz_V: 5.6; Value1: 0.5W; RJA_CperW: 350; AEC Category: Q101
D7 D8 = LED_LG L29K-G2J1-24-Z: LED SmartLED Green 570NM; Manufacturer: OSRAM; SymbolCreator: x0120606
J1 J2 J8 = ED120/2DS: as J7 on sheet TIDA-00300_ISO_Comm_PS_NM_Pg3
L1 L2 = MMZ1608B102CTA00: Ferrite Bead, 1000 ohm @ 100 MHz, 0.3 A, 0603; Manufacturer: TDK; Imax_A: 0.3; DCR_ohm: 0.6; Value1: 0.6 ohm; Value2: 0.3A; ZTyp@100MHz_Ohm: 1000
R1-R5 R82 R85 = CRCW06030000Z0EA: as R94 on sheet TIDA-00300_ISO_Comm_PS_NM_Pg3
R6 R7 = RC0603FR-07820RL: RES, 820, 1%, 0.1 W, 0603; Manufacturer: Yageo America; CompType: Resistor; Value: 820; Value_Code: 820R; Tolerance_%: 1; Power_W: 0.1; Value2: 0.1W; VDC_V: 150; TempCo: 200 ppm/C; SizeArea_mm2: 1.28; SizeX_mm: 1.6; SizeY_mm: 0.8; U/M: EA; AEC Category: Q200
R83 R84 R89 R90 R92 = CRCW06030000Z0EA: RES, 0, 5%, 0.1 W, 0603; Manufacturer: Vishay-Dale; CompType: Resistor; Value: 0; Value_Code: 0000; Tolerance_%: 5; Power_W: 0.1; Value2: 0.1W; VDC_V: 75; TempCo: 200 ppm/C; EIA_Code: E24; U/M: EA
R86 R87 = CRCW0603274KFKEA: RES, 274 k, 1%, 0.1 W, 0603; Manufacturer: Vishay-Dale; CompType: Resistor; Value: 274k; Res_ohm: 274000; Tolerance_%: 1; Power_W: 0.1; Value2: 0.1W; VDC_V: 75; TempCo: 100 ppm/C; SizeArea_mm2: 1.28; SizeX_mm: 1.6; SizeY_mm: 0.8; EIA_Code: E96; U/M: EA; AEC Category: Q200; Green_Lifecycle: Active; Green_REACh: Passed
R88 = CRCW060331K6FKEA: RES, 31.6 k, 1%, 0.1 W, 0603; Manufacturer: Vishay-Dale; CompType: Resistor; Value: 31.6k; Res_ohm: 31600; Value_Code: 31k6; Tolerance_%: 1; Power_W: 0.1; Value2: 0.1W; VDC_V: 75; TempCo: 100 ppm/C; SizeArea_mm2: 1.28; SizeX_mm: 1.6; SizeY_mm: 0.8; EIA_Code: E96; U/M: EA; AEC Category: Q200; Green_Lifecycle: Active; Green_REACh: Passed
R91 = CRCW060327K4FKEA: RES, 27.4 k, 1%, 0.1 W, 0603; Manufacturer: Vishay-Dale; CompType: Resistor; Value: 27.4k; Res_ohm: 27400; Value_Code: 27k4; Tolerance_%: 1; Power_W: 0.1; Value2: 0.1W; VDC_V: 75; TempCo: 100 ppm/C; SizeArea_mm2: 1.28; SizeX_mm: 1.6; SizeY_mm: 0.8; EIA_Code: E96; U/M: EA; AEC Category: Q200; Green_Lifecycle: Active; Green_REACh: Passed
T1 T2 = 750313734: Transformer, 340 uH, TH; Manufacturer: Wurth Elektronik; SymbolCreator: Altium; Value: 340uH; Lp: 340; DCR_ohm: 0.419
T3 = CMP-0030718-1: Transformer, 475uH, SMT; Manufacturer: Wurth Elektronik; DCR_ohm: 0.31; Lp: 475; Ind_H: 475µH
TP1 TP2 TP7 TP8 TP55 TP59 = 5000: as TP51 on sheet TIDA-00300_ISO_Comm_PS_NM_Pg3
TP3-TP6 TP57 TP58 = 5001: as TP52 on sheet TIDA-00300_ISO_Comm_PS_NM_Pg3
TP9 TP10 = 5002: Test Point, Miniature, White, TH; Manufacturer: Keystone; CompType: Test Point Loop; ContactFinish: Silver; Green_Lifecycle: Active; Green_REACh: Passed
TP56 TP60 = 5000: Test Point, Miniature, Red, TH; Manufacturer: Keystone; CompType: Test Point Loop; ContactFinish: Silver
U1 U26 = SN6505BDBVR: LOW-NOISE 1A TRANSFORMER DRIVERS FOR ISOLATED POWER SUPPLIES, DBV0006A; Alternate PartNumber: SN6505BDBVT; Manufacturer: Texas Instruments; SymbolCreator: Altium; CompType: IC; U/M: EA
U2 = SN6501DBVR: Transformer Driver for Isolated Power Supplies, DBV0005A; Alternate PartNumber: SN6501DBVT; Manufacturer: Texas Instruments; SymbolCreator: a0411947; CompType: IC; U/M: EA
U3 = CMP-0073793-1: 150-mA, 30-V, Ultra-Low IQ, Wide Input Low-Dropout Regulator with Reverse Current Protection, DBV0005A (SOT-23-5); Alternate PartNumber: TPS70933DBVT; Alternate Manufacturer: Texas Instruments; Green_Lifecycle: Active; SizeAreaWB_mm2: 14.82; Green_REACh: Passed; U/M: EA; SizeZ_mm: 1.45; SizeX_mm: 2.8; SizeY_mm: 2.9; SizeArea_mm2: 8.12; CompType: IC
U4 = CMP-0066783-1: 150-mA, 30-V, Ultra-Low IQ, Wide Input Low-Dropout Regulator with Reverse Current Protection, DBV0005A (SOT-23-5); Alternate PartNumber: TPS70950DBVT; Alternate Manufacturer: Texas Instruments; Green_Lifecycle: Active; SizeAreaWB_mm2: 14.82; Green_REACh: Passed; U/M: EA; SizeZ_mm: 1.45; SizeX_mm: 2.8; SizeY_mm: 2.9; SizeArea_mm2: 8.12; CompType: IC
U25 = TPS7A3901DSC: Wide-VIN (±33 V), 150-mA, Spilt-Rail Output, Positive and Negative LDO Voltage Regulator with Startup Tracking, DSC0010J; Manufacturer: Texas Instruments; SymbolCreator: Altium; SizeArea_mm2: 9; SizeAreaWB_mm2: 16; SizeX_mm: 3; SizeZ_mm: 0.8; CompType: IC; U/M: EA

## Sheet TIDA-00300_ISO_Comm_PS_NM_Pg5.SchDoc
size 431 x 279 mm; Date: Not shown in title block; ApprovedBy: Not shown in title block; CheckedBy: Not shown in title block; Author: Not shown in title block; CompanyName: Not shown in title block; DrawnBy: Sreenivasa; Engineer: Not shown in title block; Organization: Not shown in title block; Address1: Not shown in title block; Address2: Not shown in title block; Address3: Not shown in title block; Address4: Not shown in title block; DocumentNumber: 1; Revision: Use project parameter SCH_Rev; SheetNumber: 5; SheetTotal: 7; PageSetup: Record=PageOptions¦CenterHorizontal=True¦CenterVertical=True¦PrintScale=0.62¦XCorrection=1.00¦YCorrection=1.00¦PrintKind=0¦BorderSize=5000000¦LeftOffset=0¦BottomOffset=0¦Orientation=2¦PaperLength=1000¦PaperWidth=1000¦Scale=100¦PaperSource=15¦PrintQuality=600¦MediaType=1¦DitherType=10¦PrintScaleMode=1¦PaperKind=Letter
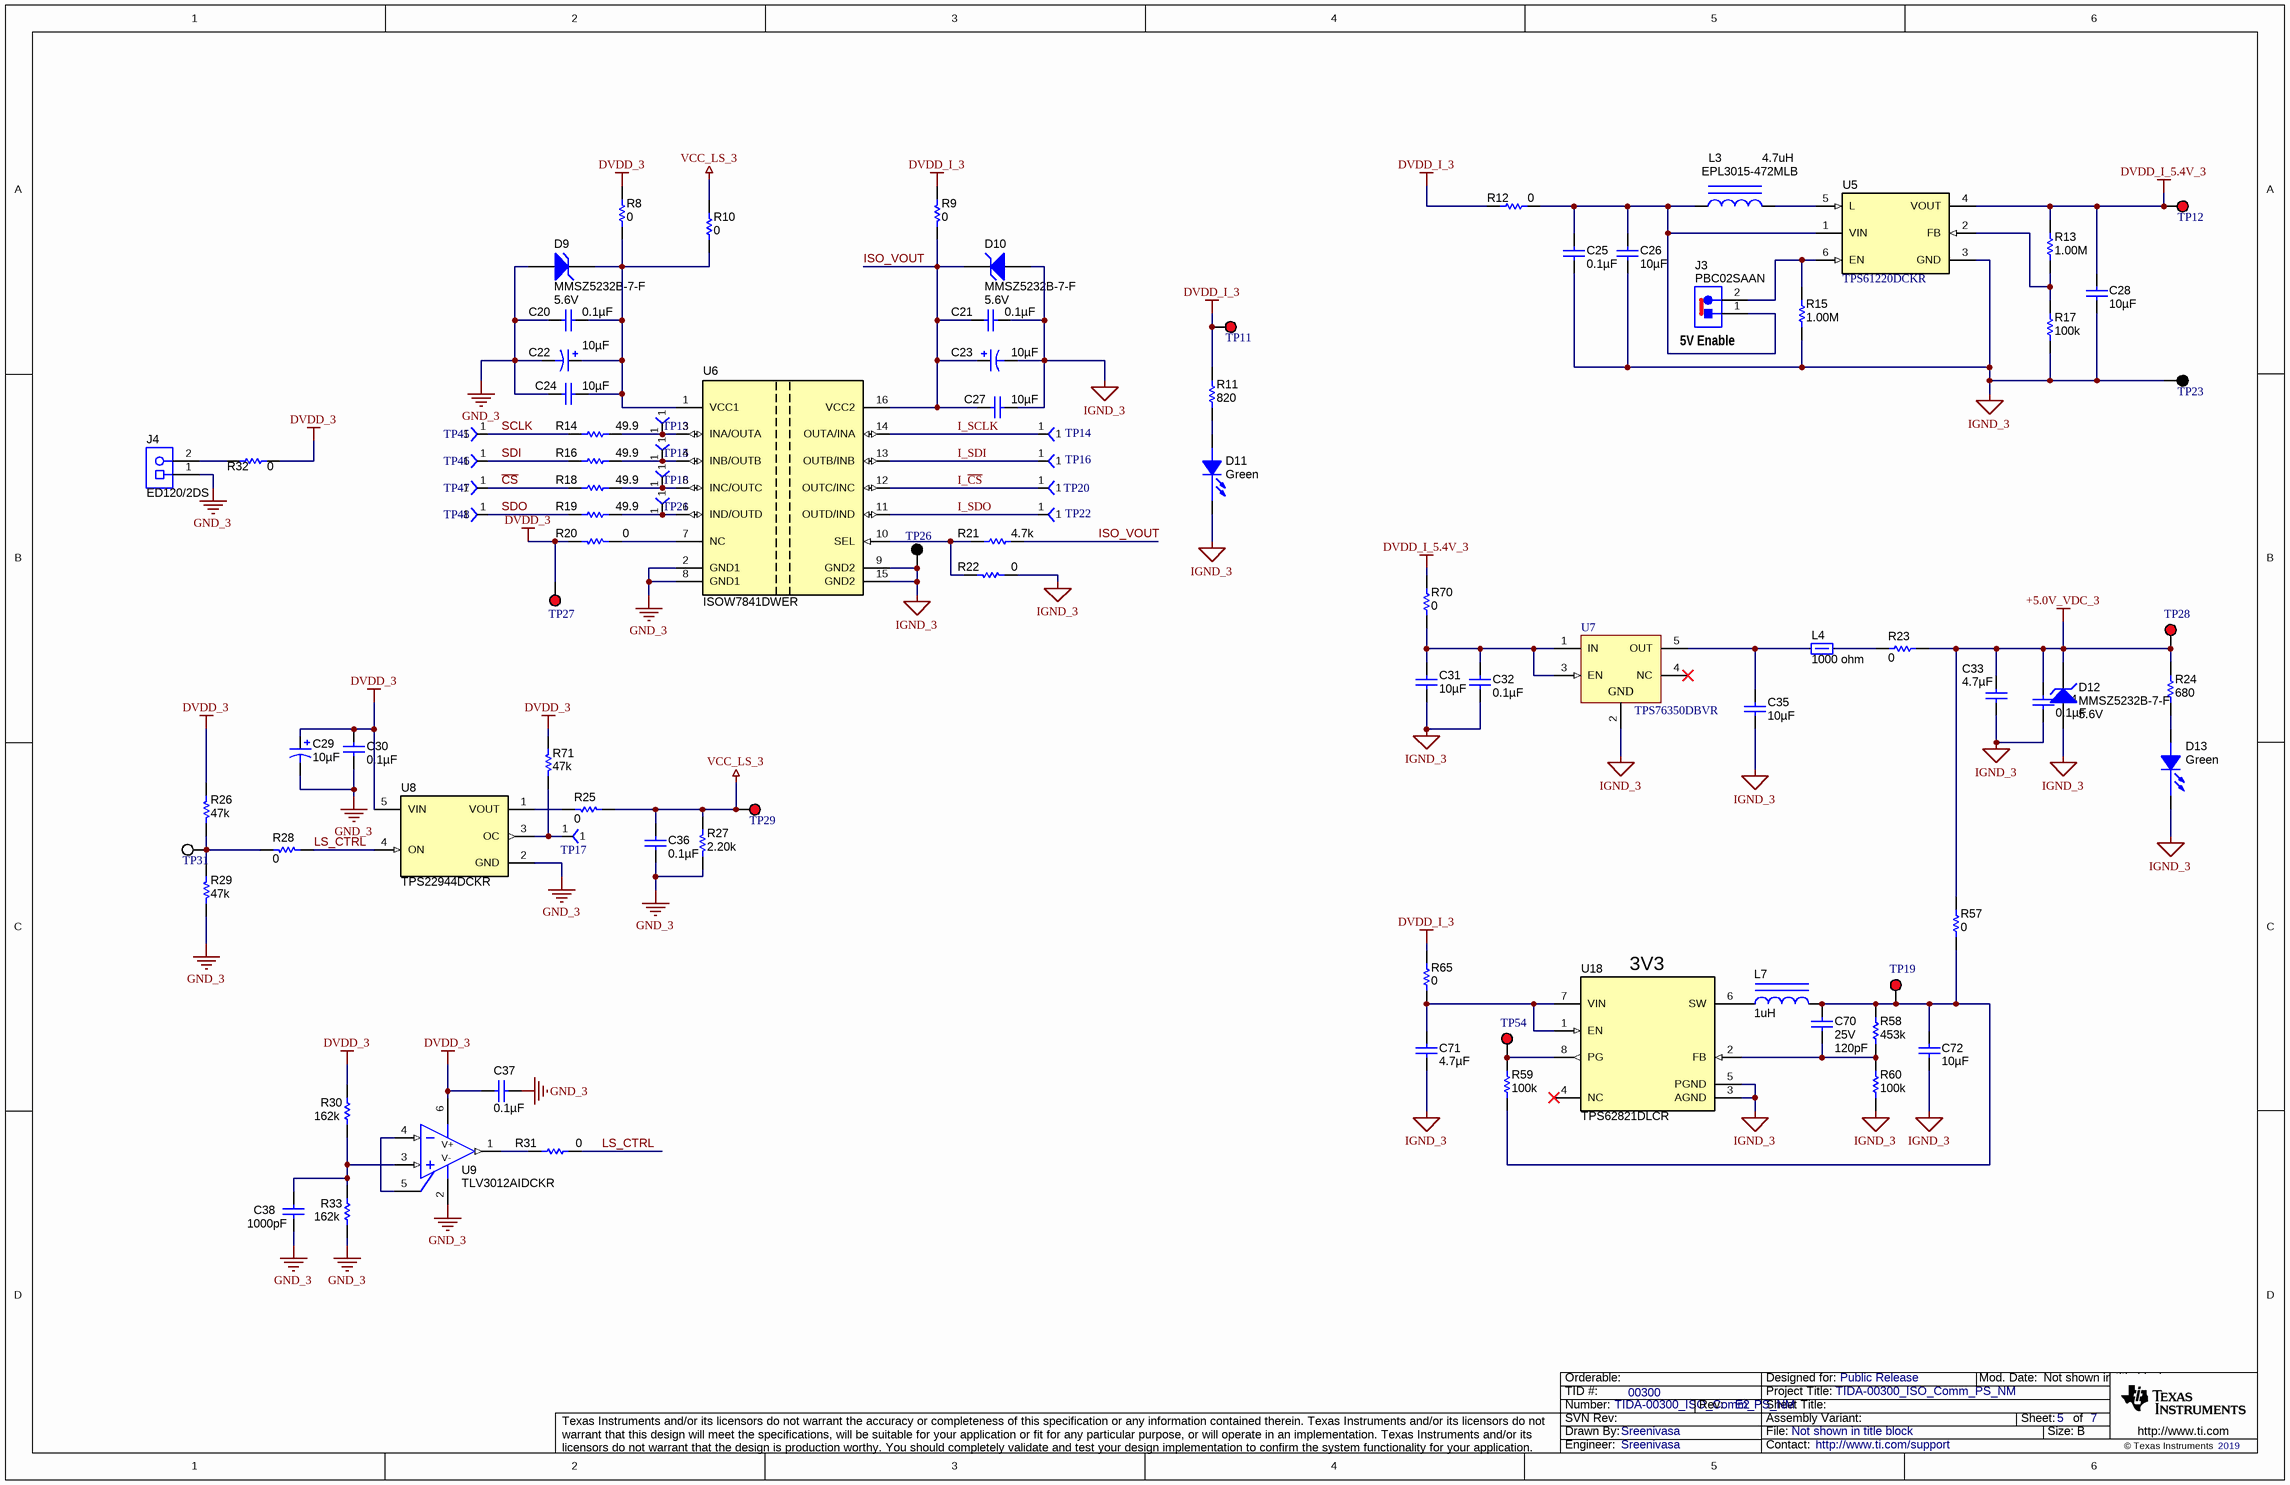
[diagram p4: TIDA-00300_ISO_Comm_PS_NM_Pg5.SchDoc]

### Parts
C20  ValueDisplayed: 0.1µF  [0603]  (hidden comment: C0603C104K5RACTU)
C21  ValueDisplayed: 0.1µF  [0603]  (hidden comment: C0603C104K5RACTU)
C22  ValueDisplayed: 10µF  [3528-21]  (hidden comment: T491B106K016AT)
C23  ValueDisplayed: 10µF  [3528-21]  (hidden comment: T491B106K016AT)
C24  ValueDisplayed: 10µF  [1206_180]  (hidden comment: GRM31CR61H106KA12L)
C25  ValueDisplayed: 0.1µF  [0402]  (hidden comment: GRM155R71A104KA01D)
C26  ValueDisplayed: 10µF  [0603]  (hidden comment: C0603C106M9PACTU)
C27  ValueDisplayed: 10µF  [1206_180]  (hidden comment: GRM31CR61H106KA12L)
C28  ValueDisplayed: 10µF  [0603]  (hidden comment: C0603C106M9PACTU)
C29  ValueDisplayed: 10µF  [3528-21]  (hidden comment: T491B106K016AT)
C30  ValueDisplayed: 0.1µF  [0603]
C31  ValueDisplayed: 10µF  [1210]
C32  ValueDisplayed: 0.1µF  [0603]
C33  ValueDisplayed: 4.7µF  [0805_HV]
C34  ValueDisplayed: 0.1µF  [0603]
C35  ValueDisplayed: 10µF  [1210]
C36  ValueDisplayed: 0.1µF  [0603]
C37  ValueDisplayed: 0.1µF  [0603]  (hidden comment: 06033C104JAT2A)
C38  ValueDisplayed: 1000pF  [0603]  (hidden comment: GRM1885C1H102JA01D)
C70  VDC_V: 25V  ValueDisplayed: 120pF  [0201]  (hidden comment: GRM033R71E121KA01D)
C71  ValueDisplayed: 4.7µF  [0603S]  (hidden comment: C1608X7S1A475K080AC)
C72  ValueDisplayed: 10µF  [0603]  (hidden comment: C0603C106M9PACTU)
D9  MMSZ5232B-7-F  value 5.6V  [SOD-123]
D10  MMSZ5232B-7-F  value 5.6V  [SOD-123]
D11  value Green  [LED0603AA]  (hidden comment: LED_LG L29K-G2J1-24-Z)
D12  MMSZ5232B-7-F  value 5.6V  [SOD-123]
D13  value Green  [LED0603AA]
J3  PBC02SAAN  [Sullins_PBC02SAAN]
J4  ED120/2DS  [CONN_ED120-2DS]
L3  EPL3015-472MLB  value 4.7uH  [EPL3015]
L4  value 1000 ohm  [MMZ1608_095]  (hidden comment: MMZ1608B102CTA00)
L7  ValueDisplayed: 1uH  [WE-PMCI_0805]  (hidden comment: 74479275210)
R8  ValueDisplayed: 0  [0603]  (hidden comment: CRCW06030000Z0EA)
R9  ValueDisplayed: 0  [0603]  (hidden comment: CRCW06030000Z0EA)
R10  ValueDisplayed: 0  [0603]  (hidden comment: CRCW06030000Z0EA)
R11  ValueDisplayed: 820  [0603]  (hidden comment: RC0603FR-07820RL)
R12  ValueDisplayed: 0  [0402]  (hidden comment: CRCW04020000Z0ED)
R13  ValueDisplayed: 1.00M  [0402]  (hidden comment: CRCW04021M00FKED)
R14  ValueDisplayed: 49.9  [0603]  (hidden comment: CRCW060349R9FKEA)
R15  ValueDisplayed: 1.00M  [0402]  (hidden comment: CRCW04021M00FKED)
R16  ValueDisplayed: 49.9  [0603]  (hidden comment: CRCW060349R9FKEA)
R17  ValueDisplayed: 100k  [0402]  (hidden comment: RC0402FR-07100KL)
R18  ValueDisplayed: 49.9  [0603]  (hidden comment: CRCW060349R9FKEA)
R19  ValueDisplayed: 49.9  [0603]  (hidden comment: CRCW060349R9FKEA)
R20  ValueDisplayed: 0  [0603]  (hidden comment: CRCW06030000Z0EA)
R21  ValueDisplayed: 4.7k  [0603]  (hidden comment: RC0603JR-074K7L)
R22  ValueDisplayed: 0  [0603]  (hidden comment: CRCW06030000Z0EA)
R23  value 0  [0603]  (hidden comment: CRCW06030000Z0EA)
R24  ValueDisplayed: 680  [0603]  (hidden comment: RC0603FR-07680RL)
R25  ValueDisplayed: 0  [0603]  (hidden comment: CRCW06030000Z0EA)
R26  ValueDisplayed: 47k  [0603]  (hidden comment: RC0603JR-0747KL)
R27  ValueDisplayed: 2.20k  [0603]  (hidden comment: RC0603FR-072K2L)
R28  value 0  [0402M]  (hidden comment: RC0402JR-070RL)
R29  ValueDisplayed: 47k  [0603]  (hidden comment: RC0603JR-0747KL)
R30  ValueDisplayed: 162k  [0603]  (hidden comment: RC0603FR-07162KL)
R31  value 0  [0402M]  (hidden comment: RC0402JR-070RL)
R32  value 0  [0402M]  (hidden comment: RC0402JR-070RL)
R33  ValueDisplayed: 162k  [0603]  (hidden comment: RC0603FR-07162KL)
R57  ValueDisplayed: 0  [0402S]  (hidden comment: RC0402JR-070RL)
R58  ValueDisplayed: 453k  [0402]  (hidden comment: CRCW0402453KFKED)
R59  ValueDisplayed: 100k  [0201]  (hidden comment: RC0201FR-07100KL)
R60  ValueDisplayed: 100k  [0402]  (hidden comment: RC0402FR-07100KL)
R65  ValueDisplayed: 0  [0402]  (hidden comment: CRCW04020000Z0ED)
R70  ValueDisplayed: 0  [0402]  (hidden comment: CRCW04020000Z0ED)
R71  ValueDisplayed: 47k  [0603]  (hidden comment: RC0603JR-0747KL)
TP11  5000  [Keystone5000]  (value not drawn)
TP12  5000  [Keystone5000]  (value not drawn)
TP13  TP-025-SMT  [TP_25MIL-SMT]  (value not drawn)
TP14  TP-025-SMT  [TP_25MIL-SMT]  (value not drawn)
TP15  TP-025-SMT  [TP_25MIL-SMT]  (value not drawn)
TP16  TP-025-SMT  [TP_25MIL-SMT]  (value not drawn)
TP17  TP-025-SMT  [TP_25MIL-SMT]  (value not drawn)
TP18  TP-025-SMT  [TP_25MIL-SMT]  (value not drawn)
TP19  5000  [Keystone5000]  (value not drawn)
TP20  TP-025-SMT  [TP_25MIL-SMT]  (value not drawn)
TP21  TP-025-SMT  [TP_25MIL-SMT]  (value not drawn)
TP22  TP-025-SMT  [TP_25MIL-SMT]  (value not drawn)
TP23  5001  [Keystone5001]  (value not drawn)
TP26  5001  [Keystone5001]  (value not drawn)
TP27  5000  [Keystone5000]  (value not drawn)
TP28  5000  [Keystone5000]  (value not drawn)
TP29  5000  [Keystone5000]  (value not drawn)
TP31  5002  [Keystone5002]  (value not drawn)
TP45  TP-025-SMT  [TP_25MIL-SMT]  (value not drawn)
TP46  TP-025-SMT  [TP_25MIL-SMT]  (value not drawn)
TP47  TP-025-SMT  [TP_25MIL-SMT]  (value not drawn)
TP48  TP-025-SMT  [TP_25MIL-SMT]  (value not drawn)
TP54  5000  [Keystone5000]  (value not drawn)
U5  TPS61220DCKR  [DCK0006A_N]
U6  ISOW7841DWER  [DW0016B_N]
U7  TPS76350DBVR  [DBV0005A_N]
U8  TPS22944DCKR  [DCK0005A_N]
U9  TLV3012AIDCKR  [DCK0006A_N]
U18  TPS62821DLCR  [DLC0008A]

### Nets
+5.0V_VDC_3: C33.2 C34.1 D12.1(K) R23.2 R24.2 R57.2 TP28.1
DVDD_3: C29.1(+) C30.2 C37.1 R8.2 R20.2 R26.2 R30.2 R32.2 R71.2 TP27.1 U8.5(VIN) U9.6(V+)
DVDD_I_3: R9.2 R11.2 R12.1 R65.2 TP11.1
DVDD_I_5.4V_3: C28.1 R13.2 R70.1 TP12.1 U5.4(VOUT)
GND_3: C20.1 C22.2(-) C24.2 C29.2(-) C30.1 C36.1 C37.2 C38.2 D9.2(A) J4.1 R27.2 R29.1 R33.1 U6.2(GND1) U6.8(GND1) U8.2(GND) U9.2(V-)
IGND_3: C21.1 C23.2(-) C25.2 C26.2 C27.1 C28.2 C31.1 C32.2 C33.1 C34.2 C35.1 C71.2 C72.2 D10.2(A) D11.1(C) D12.2(A) D13.1(C) R15.1 R17.1 R22.1 R60.1 TP23.1 TP26.1 U5.3(GND) U6.9(GND2) U6.15(GND2) U7.2(GND) U18.3(AGND) U18.5(PGND)
VCC_LS_3: C36.2 R10.2 R25.1 R27.1 TP29.1
~{CS}: R18.2 TP47.1
I_~{CS}: TP20.1 U6.12(OUTC/INC)
I_SCLK: TP14.1 U6.14(OUTA/INA)
I_SDI: TP16.1 U6.13(OUTB/INB)
I_SDO: TP22.1 U6.11(OUTD/IND)
ISO_VOUT: C21.2 C23.1(+) C27.2 D10.1(K) R9.1 R21.1 U6.16(VCC2)
LS_CTRL: R28.1 R31.2 U8.4(ON)
SCLK: R14.2 TP45.1
SDI: R16.2 TP46.1
SDO: R19.2 TP48.1
NetC20_2: C20.2 C22.1(+) C24.1 D9.1(K) R8.1 R10.1 U6.1(VCC1)
NetC25_1: C25.1 C26.1 J3.1 L3.1 R12.2 U5.1(VIN)
NetC31_2: C31.2 C32.1 R70.2 U7.1(IN) U7.3(EN)
NetC35_2: C35.2 L4.1 U7.5(OUT)
NetC38_1: C38.1 R30.1 R33.2 U9.3(IN+)
NetC70_1: C70.1 C72.1 L7.2 R57.1 R58.2 R59.1 TP19.1
NetC70_2: C70.2 R58.1 R60.2 U18.2(FB)
NetC71_1: C71.1 R65.1 U18.1(EN) U18.7(VIN)
NetD11_2: D11.2(A) R11.1
NetD13_2: D13.2(A) R24.1
NetJ3_2: J3.2 R15.2 U5.6(EN)
NetJ4_2: J4.2 R32.1
NetL3_2: L3.2 U5.5(L)
NetL4_2: L4.2 R23.1
NetL7_1: L7.1 U18.6(SW)
NetR13_1: R13.1 R17.2 U5.2(FB)
NetR14_1: R14.1 TP13.1 U6.3(INA/OUTA)
NetR16_1: R16.1 TP15.1 U6.4(INB/OUTB)
NetR18_1: R18.1 TP18.1 U6.5(INC/OUTC)
NetR19_1: R19.1 TP21.1 U6.6(IND/OUTD)
NetR20_1: R20.1 U6.7(NC)
NetR21_2: R21.2 R22.2 U6.10(SEL)
NetR25_2: R25.2 U8.1(VOUT)
NetR26_1: R26.1 R28.2 R29.2 TP31.1
NetR31_1: R31.1 U9.1(OUT)
NetR59_2: R59.2 TP54.1 U18.8(PG)
NetR71_1: R71.1 TP17.1 U8.3(OC)
NetU9_4: U9.4(IN-) U9.5(REF)

Not connected (* = marked no-connect by the designer): U7 4(NC)*; U18 4(NC)*

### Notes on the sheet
- (near J3) 5V Enable
- (near U18) 3V3

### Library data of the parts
C20 C21 C30 C32 C34 C36 = C0603C104K5RACTU: as C3 on sheet TIDA-00300_ISO_Comm_PS_NM_Pg4
C22 C23 C29 = 293D106X9016B2TE3: CAP, TA, 10 µF, 16 V, +/- 10%, 2 ohm, SMD; Manufacturer: Vishay-Sprague; Polarized: Y; CompType: Capacitor; Value: 10uF; U/M: EA; Cap_F: 0.00001; Tolerance_%: 10; Value1: 2 ohm; VDC_V: 16; Value2: 16V; ESR_ohm: 2; IRMS_A: 0.21; TaMin_C: -55; TaMax_C: 125; Cap_Case: B
C24 C27 = GRM31CR61H106KA12L: CAP, CERM, 10 µF, 50 V, +/- 10%, X5R, 1206; Manufacturer: MuRata; Polarized: N; CompType: Capacitor; Value: 10uF; U/M: EA; Cap_F: 0.00001; Tolerance_%: 10; Value1: Unknown; VDC_V: 50; Value2: 50V; TaMin_C: -55; TaMax_C: 85; Cap_Case: 1206; SizeArea_mm2: 5.12; SizeAreaWB_mm2: 10.92; SizeX_mm: 3.2; SizeY_mm: 1.6; SizeZ_mm: 1.8; AEC Category: Q200
C25 = GRM155R71A104KA01D: CAP, CERM, 0.1uF, 10V, +/-10%, X7R, 0402; Manufacturer: MuRata; Polarized: N; CompType: Capacitor; U/M: EA; Cap_F: 0.0000001; Tolerance_%: 10; Value1: Unknown; TaMin_C: -55; TaMax_C: 125
C26 C28 C72 = C0603C106M9PACTU: CAP, CERM, 10 µF, 6.3 V, +/- 20%, X5R, 0603; Manufacturer: Kemet; Polarized: N; CompType: Capacitor; Value: 10uF; U/M: EA; Cap_F: 0.00001; Tolerance_%: 20; ESR_ohm: 0.004; Value1: 0.004 ohm; VDC_V: 6.3; Value2: 6.3V; IRMS_A: 8.9; TaMin_C: -55; TaMax_C: 85
C31 C35 = GMK325AB7106MM-T: as C1 on sheet TIDA-00300_ISO_Comm_PS_NM_Pg4
C33 = C2012X5R1H475K125AB: as C14 on sheet TIDA-00300_ISO_Comm_PS_NM_Pg4
C37 = 06033C104JAT2A: CAP, CERM, 0.1 µF, 25 V, +/- 5%, X7R, 0603; Manufacturer: AVX; Polarized: N; CompType: Capacitor; Value: 0.1uF; U/M: EA; Cap_F: 0.0000001; Tolerance_%: 5; ESR_ohm: 0.05; Value1: 0.05 ohm; VDC_V: 25; Value2: 25V; TaMin_C: -55; TaMax_C: 125
C38 = GRM1885C1H102JA01D: CAP, CERM, 1000 pF, 50 V, +/- 5%, C0G/NP0, 0603; Manufacturer: MuRata; Polarized: N; CompType: Capacitor; Value: 1000pF; U/M: EA; Cap_F: 0.000000001; Tolerance_%: 5; Value1: Unknown; VDC_V: 50; Value2: 50V; TaMin_C: -55; TaMax_C: 125; AEC Category: Q200
C70 = CMP-0009765-1: CAP, CERM, 120 pF, 25 V, +/- 10%, X7R, 0201; Manufacturer: MuRata; TaMin_C: -55°C; Polarized: N; SizeAreaWB_mm2: 2.08; Value1: Unknown; U/M: EA; Value: 120pF; TaMax_C: 125°C; SizeZ_mm: 0.26; SizeX_mm: 0.6; SizeY_mm: 0.3; SizeArea_mm2: 0.18; AEC Category: Q200
C71 = C1608X7S1A475K080AC: CAP, CERM, 4.7 µF, 10 V,+/- 10%, X7S, 0603; Manufacturer: TDK; Polarized: N; CompType: Capacitor; Value: 4.7uF; U/M: EA; Cap_F: 0.0000047; Tolerance_%: 10; Value2: 10V; TaMin_C: -55; TaMax_C: 125; Cap_Case: 0603; SizeArea_mm2: 1.28; SizeAreaWB_mm2: 4.68; SizeX_mm: 1.6; SizeY_mm: 0.8; SizeZ_mm: 1; AEC Category: Q200; Green_Lifecycle: Active; Green_REACh: Passed
D9 D10 D12 = MMSZ5232B-7-F: as D5 on sheet TIDA-00300_ISO_Comm_PS_NM_Pg4
D11 = LED_LG L29K-G2J1-24-Z: LED GREEN DIFFUSED 0603 SMD; PartNumber: SML-D12M8WT86; Manufacturer: ROHM Semiconductor; SymbolCreator: x0120606
D13 = LED_LG L29K-G2J1-24-Z: as D7 on sheet TIDA-00300_ISO_Comm_PS_NM_Pg4
J3 = PBC02SAAN: Header, 100mil, 2x1, Gold, TH; Manufacturer: Sullins Connector Solutions; SymbolCreator: a0412235; U/M: EA
J4 = ED120/2DS: as J7 on sheet TIDA-00300_ISO_Comm_PS_NM_Pg3
L3 = EPL3015-472MLB: Inductor, Shielded, Ferrite, 4.7 µH, 1.2 A, 0.14 ohm, SMD; Manufacturer: Coilcraft; Ind_H: 4.7E-6; ValueDisplayed: 4.7µH; Imax_A: 1.2; Irms: 1.4A @ 40C rise; Isat: 1.2A @ 30% inductance drop; DCR_ohm: 0.14; Value2: 1.2A
L4 = MMZ1608B102CTA00: as L1 on sheet TIDA-00300_ISO_Comm_PS_NM_Pg4
L7 = CMP-0064308-1: Inductor, Shielded, 1 uH, 1.8 A, 0.078 ohm, SMD; Manufacturer: Wurth Elektronik; Isat: 2.1A @ 30% inductance drop; Irms: 1.8A @ 40C rise; Green_Lifecycle: Active; SizeAreaWB_mm2: 6.75; DCR_ohm: 0.078; Green_REACh: Passed; Value: 1uH; Imax_A: 1.8A; SizeZ_mm: 1; SizeX_mm: 2; SizeY_mm: 1.25; SizeArea_mm2: 2.5; Ind_H: 1µH; AEC Qualified: N; AEC Category: Q200
R8-R10 R20 R22 R25 = CRCW06030000Z0EA: as R83 on sheet TIDA-00300_ISO_Comm_PS_NM_Pg4
R11 = RC0603FR-07820RL: as R6 on sheet TIDA-00300_ISO_Comm_PS_NM_Pg4
R12 R65 R70 = CRCW04020000Z0ED: RES, 0, 5%, 0.063 W, 0402; Manufacturer: Vishay-Dale; CompType: Resistor; Value: 0; Value_Code: 0000; Tolerance_%: 5; Power_W: 0.063; Value2: 0.063W; VDC_V: 50; TempCo: 200 ppm/C; EIA_Code: E24; U/M: EA
R13 R15 = CRCW04021M00FKED: RES, 1.00 M, 1%, 0.063 W, 0402; Manufacturer: Vishay-Dale; CompType: Resistor; Value: 1.00Meg; Res_ohm: 1000000; Value_Code: 1M00; Tolerance_%: 1; Power_W: 0.063; Value2: 0.063W; VDC_V: 50; TempCo: 100 ppm/C; EIA_Code: E96; U/M: EA
R14 R16 R18 R19 = CRCW060349R9FKEA: RES, 49.9, 1%, 0.1 W, 0603; Manufacturer: Vishay-Dale; CompType: Resistor; Value: 49.9; Value_Code: 49R9; Tolerance_%: 1; Power_W: 0.1; Value2: 0.1W; VDC_V: 75; TempCo: 100 ppm/C; SizeArea_mm2: 1.28; SizeX_mm: 1.6; SizeY_mm: 0.8; EIA_Code: E96; U/M: EA; AEC Category: Q200
R17 R60 = RC0402FR-07100KL: RES, 100 k, 1%, 0.0625 W, 0402; Manufacturer: Yageo America; CompType: Resistor; Value: 100k; Res_ohm: 100000; Tolerance_%: 1; Power_W: 0.0625; VDC_V: 50; TempCo: 100 ppm/C; SizeArea_mm2: 0.5; SizeZ_mm: 0.6; EIA_Code: E96; U/M: EA; AEC Category: Q200; AEC Qualified: N; Green_Lifecycle: Active; Green_REACh: Passed
R21 = RC0603JR-074K7L: RES, 4.7 k, 5%, 0.1 W, 0603; Manufacturer: Yageo America; CompType: Resistor; Value: 4.7k; Res_ohm: 4700; Value_Code: 4k70; Tolerance_%: 5; Power_W: 0.1; Value2: 0.1W; VDC_V: 50; TempCo: 100 ppm/C; SizeArea_mm2: 1.28; SizeX_mm: 1.6; SizeY_mm: 0.8; SizeZ_mm: 1; EIA_Code: E24; U/M: EA; AEC Category: Q200
R23 = CRCW06030000Z0EA: as R94 on sheet TIDA-00300_ISO_Comm_PS_NM_Pg3
R24 = RC0603FR-07680RL: RES, 680, 1%, 0.1 W, 0603; Manufacturer: Yageo America; CompType: Resistor; Value: 680; Value_Code: 680R; Tolerance_%: 1; Power_W: 0.1; Value2: 0.1W; VDC_V: 150; TempCo: 200 ppm/C; SizeArea_mm2: 1.28; SizeX_mm: 1.6; SizeY_mm: 0.8; U/M: EA; AEC Category: Q200; Green_Lifecycle: Active; Green_REACh: Passed
R26 R29 R71 = RC0603JR-0747KL: RES, 47 k, 5%, 0.1 W, 0603; Manufacturer: Yageo America; CompType: Resistor; Value: 47k; Res_ohm: 47000; Value_Code: 47k0; Tolerance_%: 5; Power_W: 0.1; Value2: 0.1W; VDC_V: 50; TempCo: 100 ppm/C; EIA_Code: E24; U/M: EA
R27 = RC0603FR-072K2L: RES, 2.20 k, 1%, 0.1 W, 0603; Manufacturer: Yageo America; CompType: Resistor; Value: 2.20k; Res_ohm: 2200; Value_Code: 2k20; Tolerance_%: 1; Power_W: 0.1; Value2: 0.1W; VDC_V: 150; TempCo: 200 ppm/C; U/M: EA
R28 R31 R32 = RC0402JR-070RL: RES, 0 ohm, 5%, 0.063W, 0402; Manufacturer: Yageo America; CompType: Resistor; Value_Code: 0000; Tolerance_%: 5; Power_W: 0.063; VDC_V: 50; TempCo: 200 ppm/C; EIA_Code: E24; U/M: EA
R30 R33 = RC0603FR-07162KL: RES, 162 k, 1%, 0.1 W, 0603; Manufacturer: Yageo America; CompType: Resistor; Value: 162k; Res_ohm: 162000; Tolerance_%: 1; Power_W: 0.1; Value2: 0.1W; VDC_V: 150; TempCo: 200 ppm/C; EIA_Code: E96; U/M: EA
R57 = CMP-0027004-2: RES, 0, 5%, 0.063 W, 0402; Manufacturer: Yageo America; Power_W: 63mW; TempCo: 200 ppm/C; Value_Code: 0000; U/M: EA; Value: 0; EIA_Code: E24; SizeX_mm: 1; SizeY_mm: 0.5; SizeZ_mm: 0.6; Value2: 0.063W; VDC_V: 50V; AEC Category: Q200
R58 = CRCW0402453KFKED: RES, 453 k, 1%, 0.063 W, 0402; Manufacturer: Vishay-Dale; CompType: Resistor; Value: 453k; Res_ohm: 453000; Tolerance_%: 1; Power_W: 0.063; Value2: 0.063W; VDC_V: 50; TempCo: 100 ppm/C; SizeArea_mm2: 0.5; SizeZ_mm: 0.6; EIA_Code: E96; U/M: EA; AEC Category: Q200
R59 = CMP-0027293-2: RES, 100 k, 1%, 0.05 W, 0201; Manufacturer: Yageo America; Power_W: 50mW; TempCo: 200 ppm/C; U/M: EA; Value: 100k; EIA_Code: E96; SizeX_mm: 0.6; SizeY_mm: 0.3; SizeZ_mm: 0.26; Value2: 0.05W; SizeArea_mm2: 0.18; AEC Qualified: N; VDC_V: 25V; AEC Category: Q200
TP11 TP12 TP19 TP27-TP29 TP54 = 5000: as TP51 on sheet TIDA-00300_ISO_Comm_PS_NM_Pg3
TP13-TP18 TP20-TP22 TP45-TP48 = TP-025-SMT: Test Point, O.025"; Manufacturer: STD; Value: STD
TP23 TP26 = 5001: as TP52 on sheet TIDA-00300_ISO_Comm_PS_NM_Pg3
TP31 = 5002: as TP9 on sheet TIDA-00300_ISO_Comm_PS_NM_Pg4
U5 = CMP-0067204-1: Low Input Voltage, 0.7V Boost Converter with 5.5uA Quiescent Current, DCK0006A (SOT-SC70-6); Alternate PartNumber: TPS61220DCKT; Alternate Manufacturer: Texas Instruments; Green_Lifecycle: Active; SizeAreaWB_mm2: 9.3; Green_REACh: Passed; U/M: EA; SizeZ_mm: 1.1; SizeX_mm: 2.1; SizeY_mm: 2.0; SizeArea_mm2: 4.2; CompType: IC
U6 = ISOW7841DWR: ISOW7841DWE, DW0016B (SOIC-16); Manufacturer: Texas Instruments; SymbolCreator: a0411947; SizeArea_mm2: 107.12; SizeAreaWB_mm2: 152.52; SizeX_mm: 10.4; SizeY_mm: 10.3; SizeZ_mm: 2.65; CompType: IC; U/M: EA
U7 = CMP-0035560-1: Single Output LDO, 150 mA, Fixed 5 V Output, 2.7 to 10 V Input, with Low IQ, 5-pin SOT-23 (DBV), -40 to 125 degC, Green (RoHS & no Sb/Br); Manufacturer: Texas Instruments; Vout Adj(Min)(V): 5; SubFamily: Single Channel LDO; Iq(Typ)(mA): 0.08; Vin(Max)(V): 10; Vdo(Typ)(mV): 300; Iout(Max)(A): 0.15; Vin(Min)(V): 2.7; Accuracy(%): 3
U8 = TPS22944DCKR: LOW-INPUT-VOLTAGE CURRENT-LIMITED LOAD SWITCHES WITH SHUT OFF AND AUTO-RESTART FEATURE, DCK0005A (SOT-5); Manufacturer: Texas Instruments; SymbolCreator: a0411947; SizeArea_mm2: 4.2; SizeAreaWB_mm2: 9.3; SizeX_mm: 2.1; SizeY_mm: 2; SizeZ_mm: 1.1; CompType: IC; U/M: EA
U9 = TLV3012AIDCKR: Nanopower, 1.8V, Comparator with Voltage Reference, DCK0006A; Alternate PartNumber: TLV3012AIDCKT; Manufacturer: Texas Instruments; SymbolCreator: a0411595/a0412235; CompType: IC; U/M: EA
U18 = CMP-0065148-3: 1A Step-Down Converter With 1% Accuracy, DLC0008A (VSON-HR-8); Manufacturer: Texas Instruments; SizeX_mm: 1.5; SizeY_mm: 2.0; CompType: IC; SizeZ_mm: 1.0; SizeArea_mm2: 3.0; SizeAreaWB_mm2: 7.5; AEC Category: Q200; AEC Qualified: N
